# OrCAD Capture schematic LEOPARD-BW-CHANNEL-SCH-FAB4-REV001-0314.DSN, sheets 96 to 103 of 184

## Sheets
96 078_CPU SIDE BAND - FIVR FAULT: size A3; title: CPU SIDE BAND - FIVR FAULT
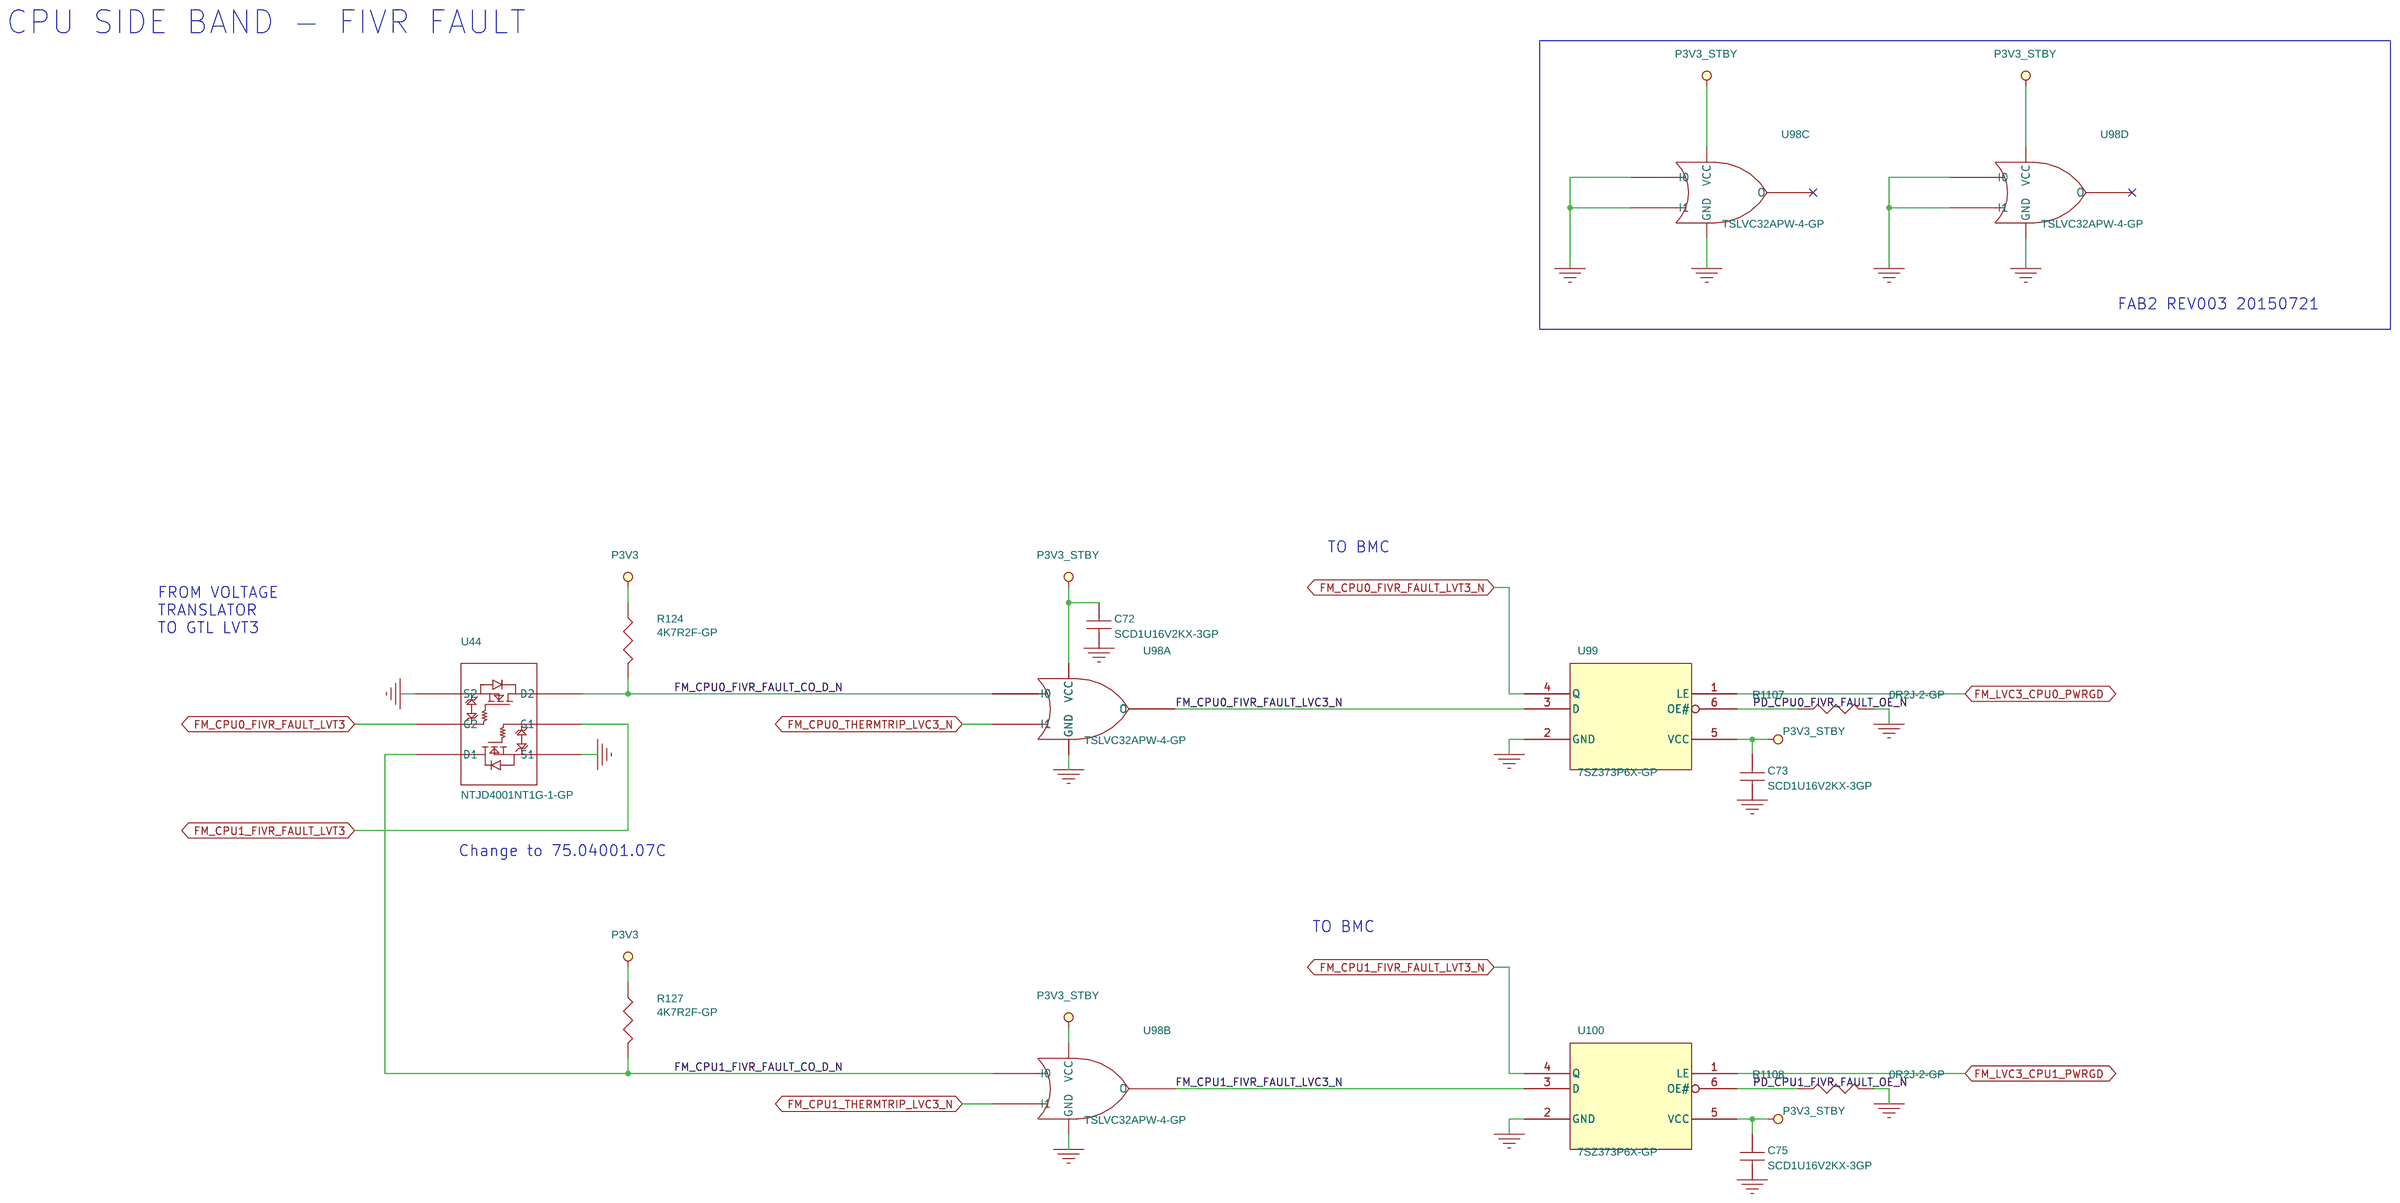
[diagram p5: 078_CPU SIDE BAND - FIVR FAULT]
97 076_CPU SIDE BAND - RST & PG: size A3; title: CPU SIDE BAND - RST & PG
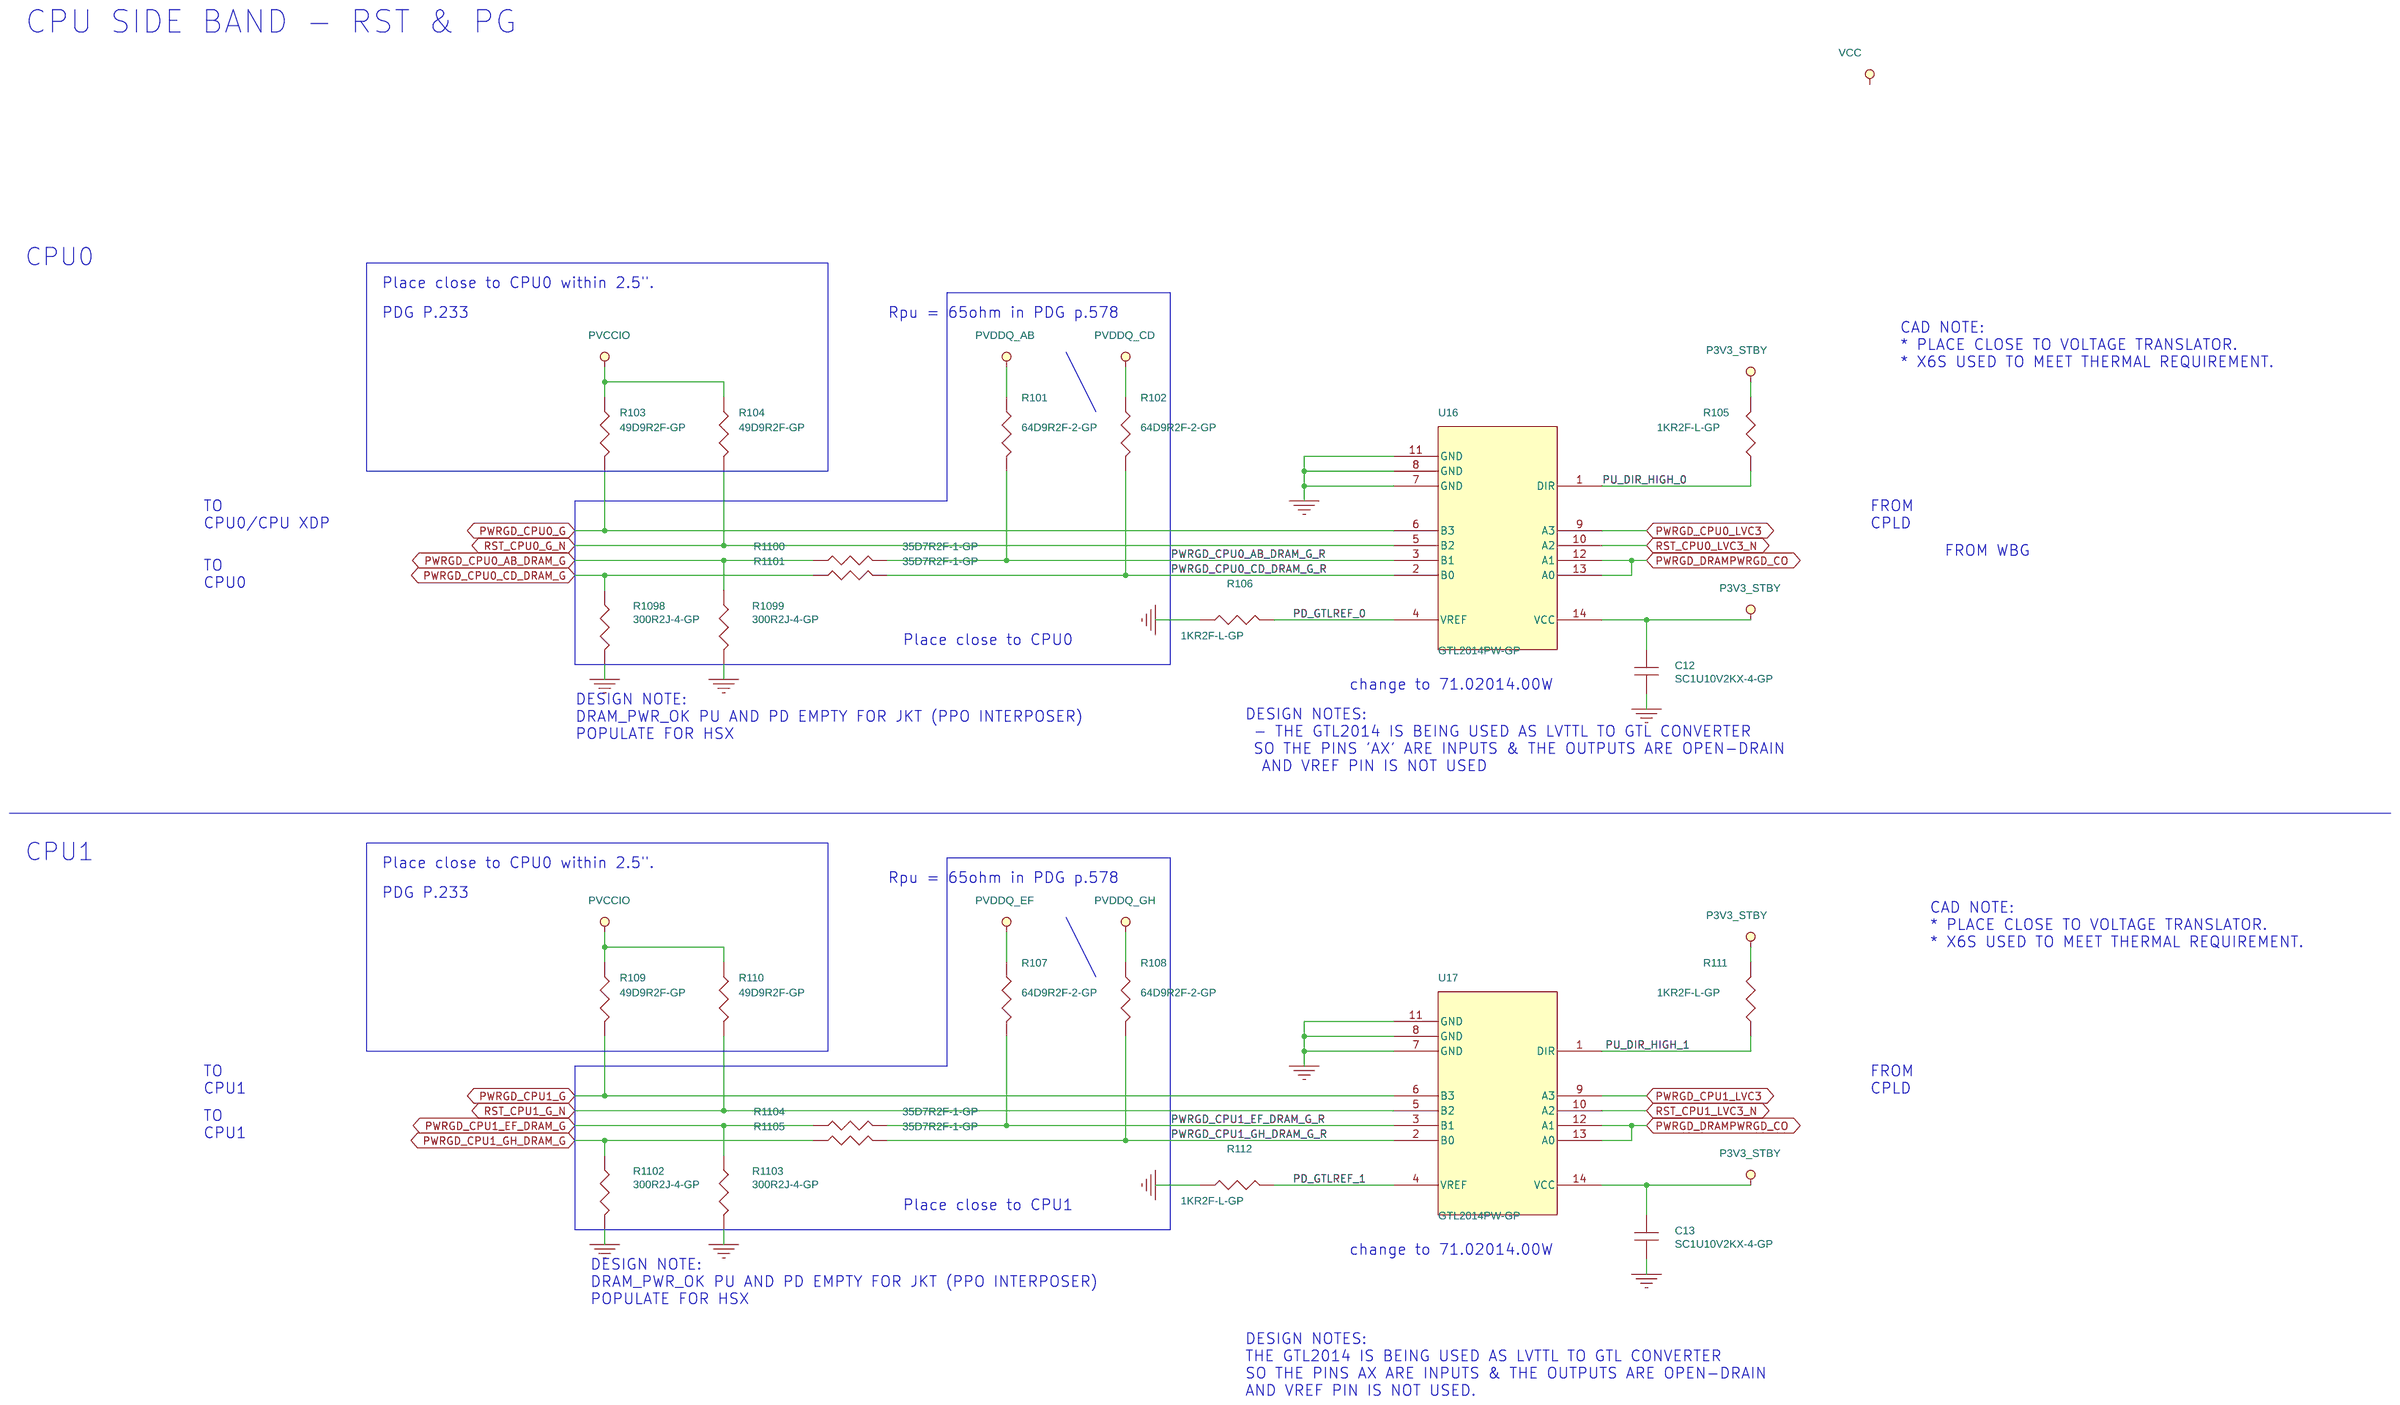
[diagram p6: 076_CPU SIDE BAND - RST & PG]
98 075_CPU SIDE BAND - DIMM_EVENT: size A3; title: CPU SIDE BAND - DIMM EVENT
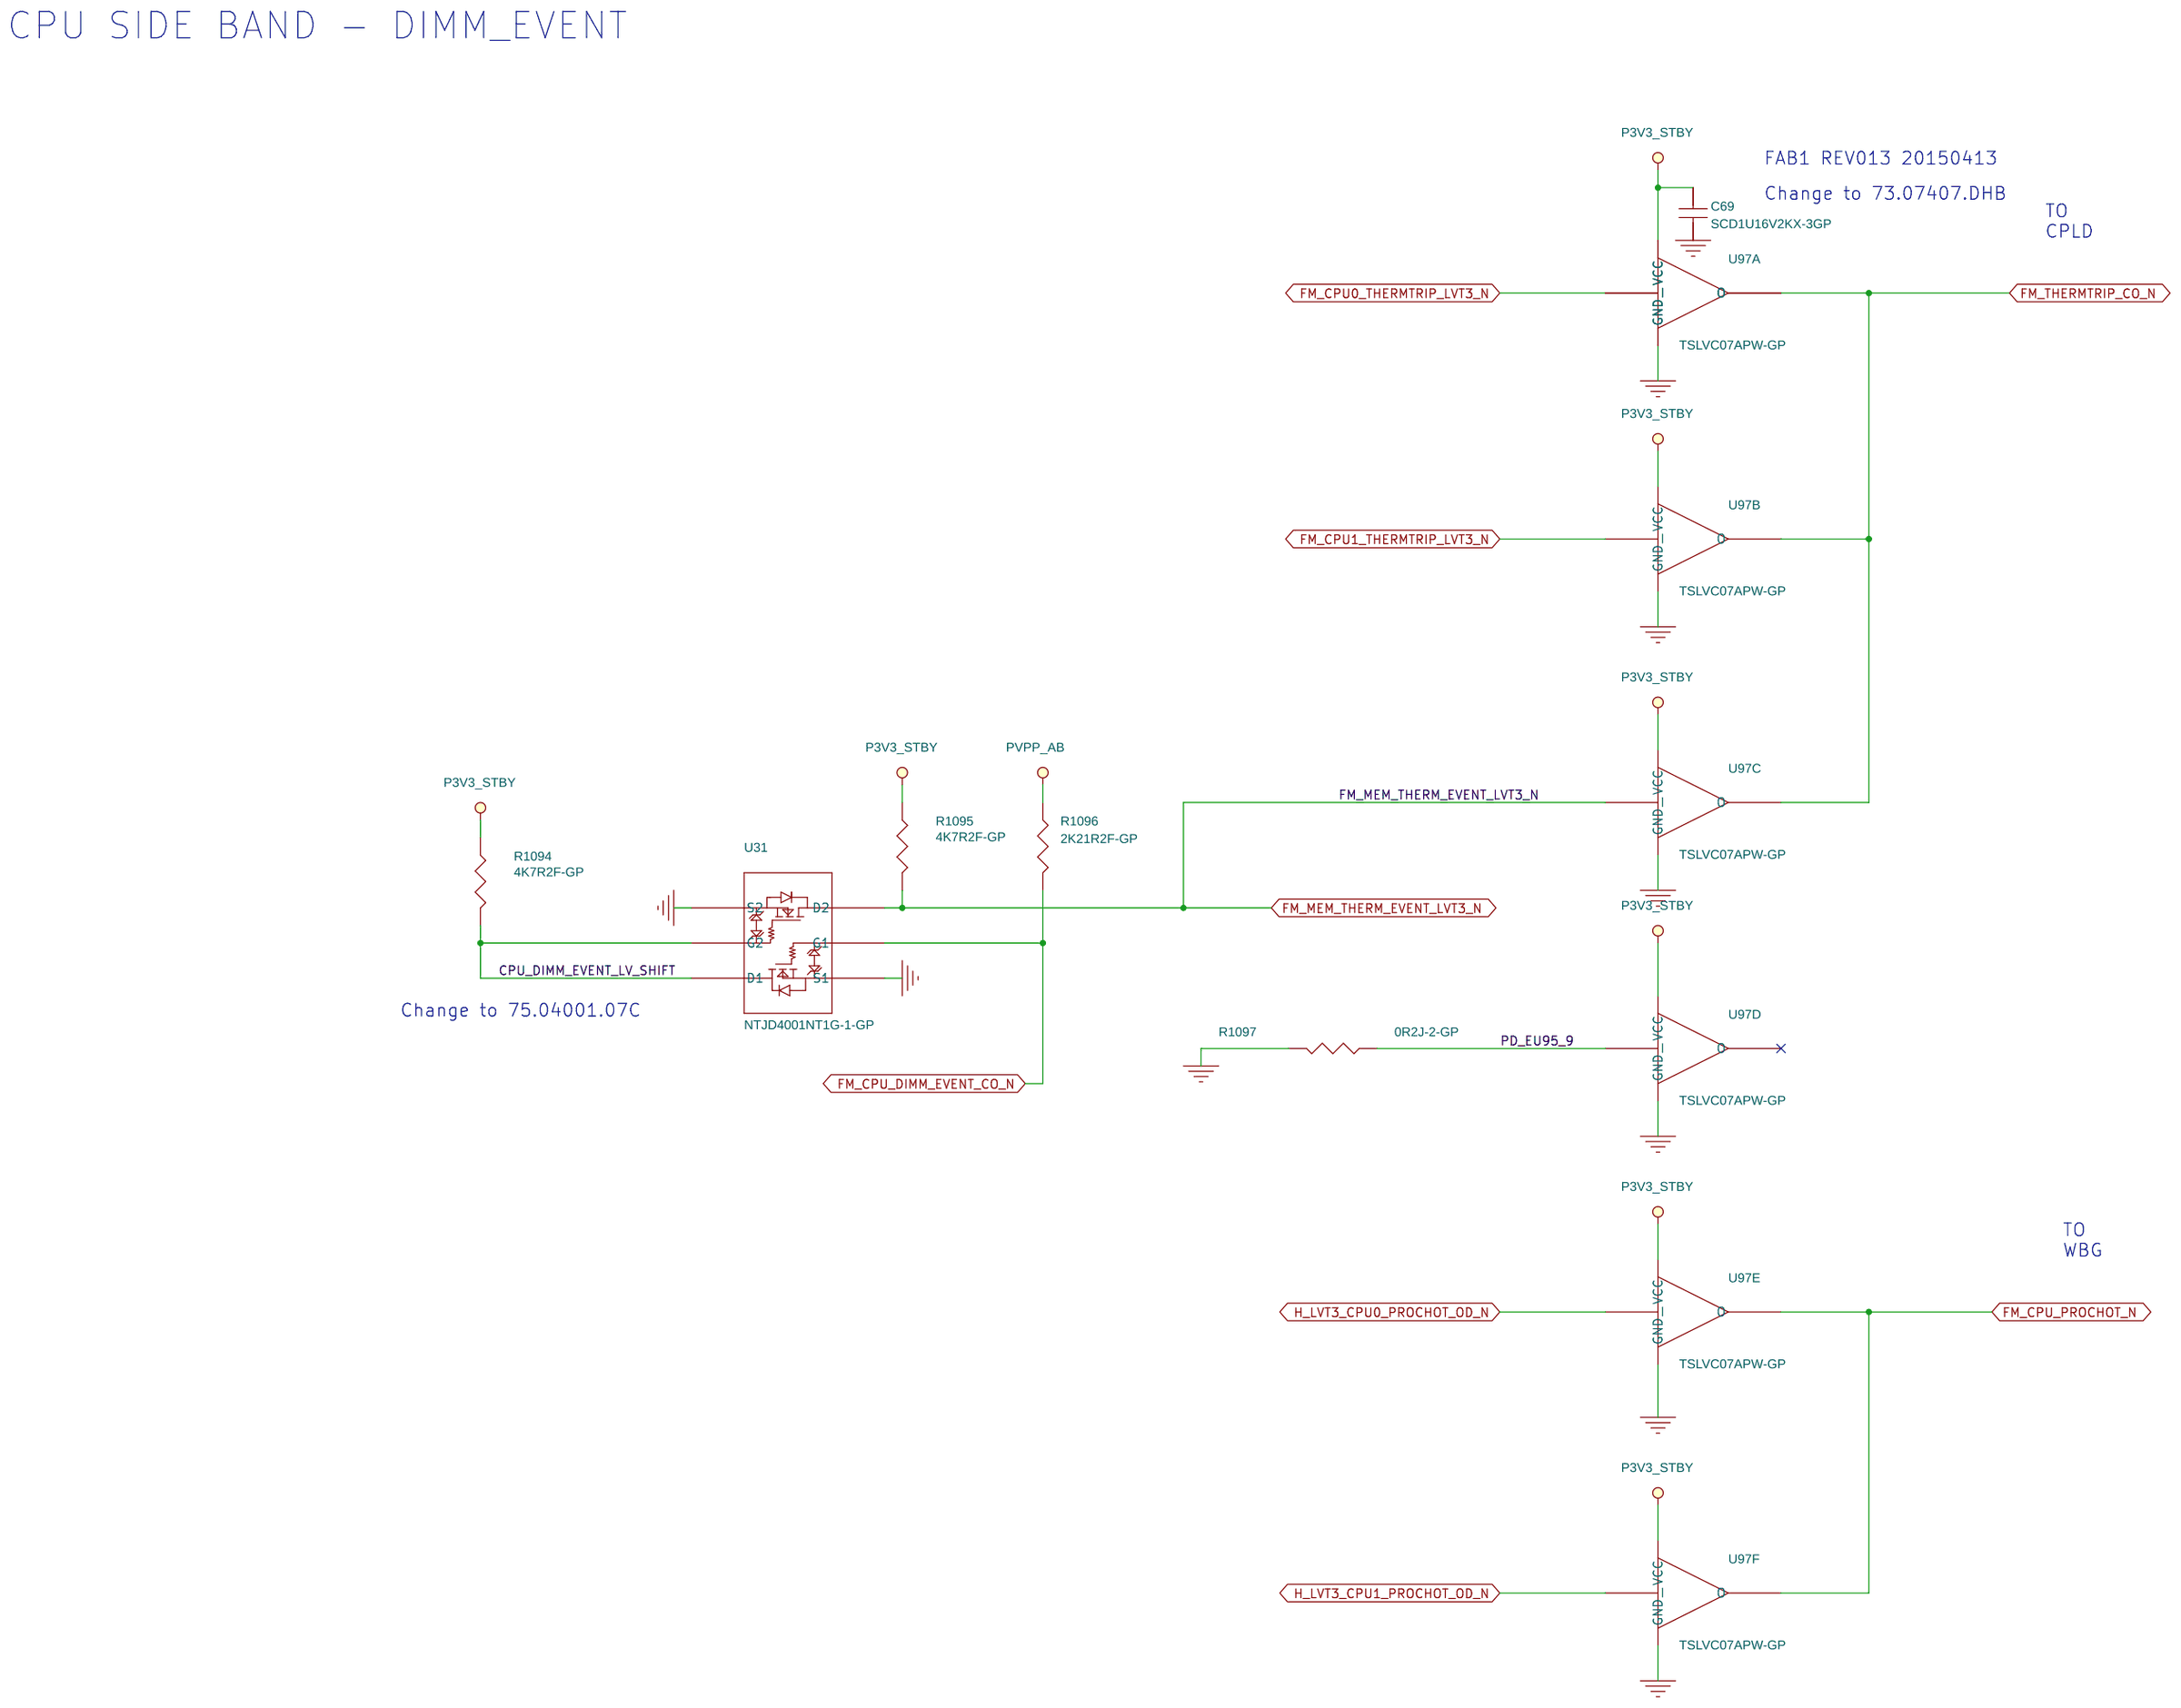
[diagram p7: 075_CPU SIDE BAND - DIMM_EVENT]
99 072_CPU SIDE BAND - THERMTRIP: size A3; title: CPU SIDE BAND - THERMTRIP
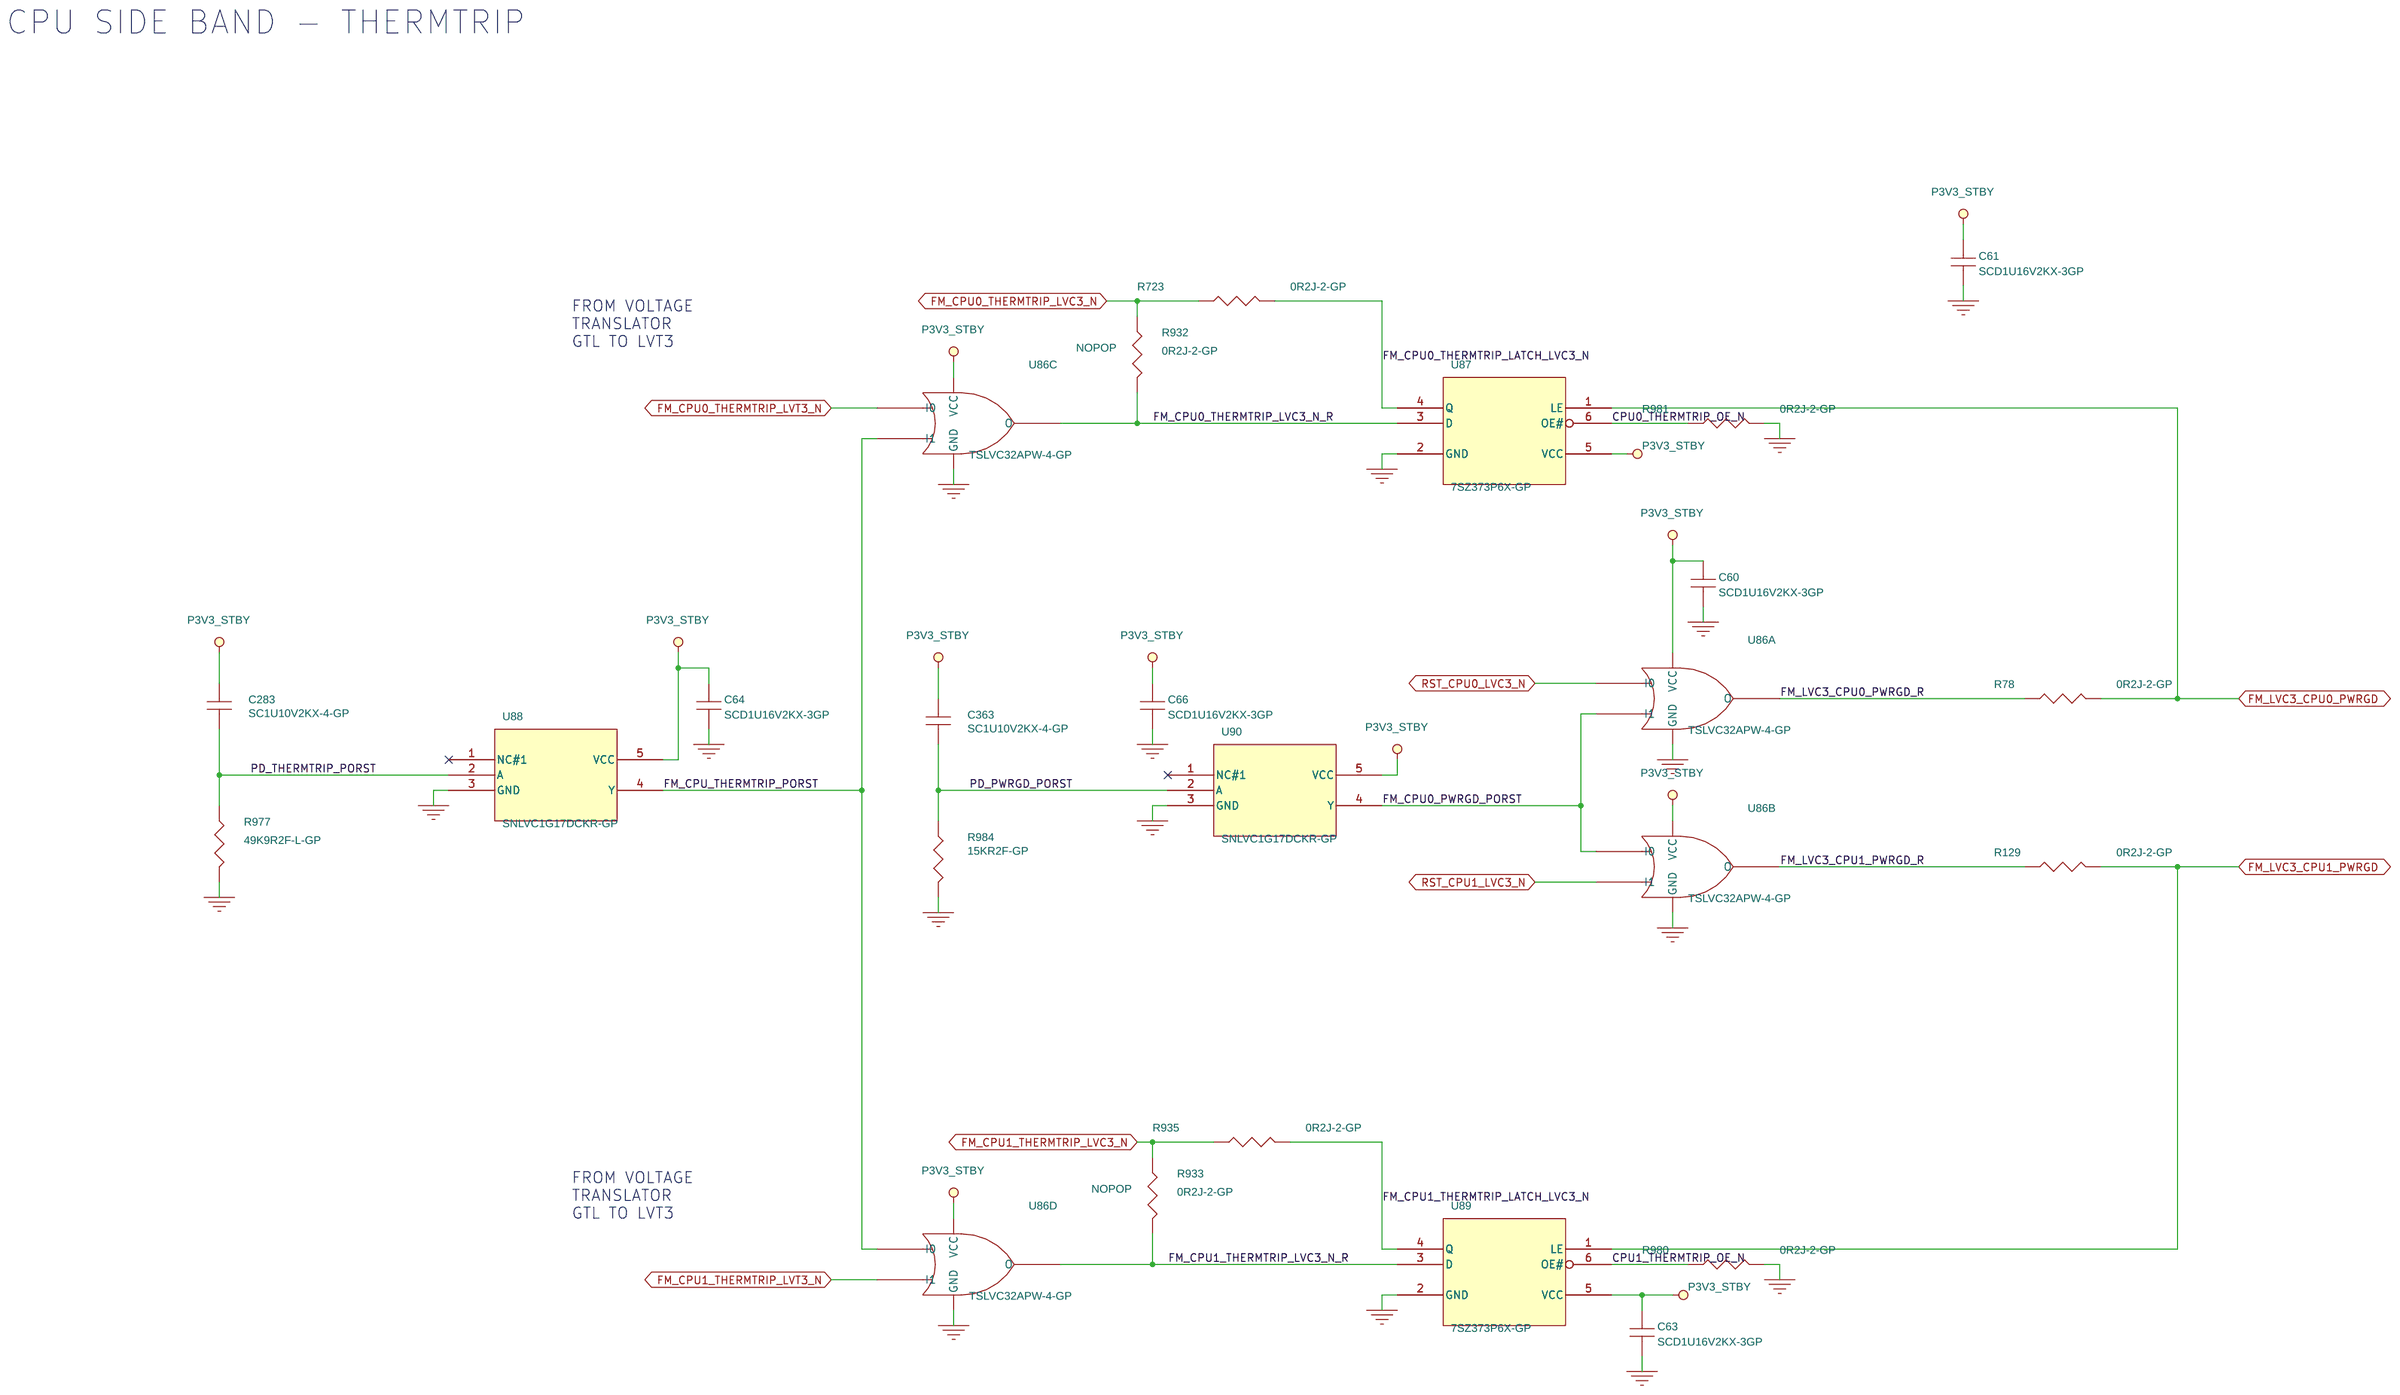
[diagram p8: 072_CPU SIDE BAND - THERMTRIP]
100 071_CPU SIDE BAND - CAT. ERROR: size A3; title: CPU SIDE BAND - CAT. ERROR
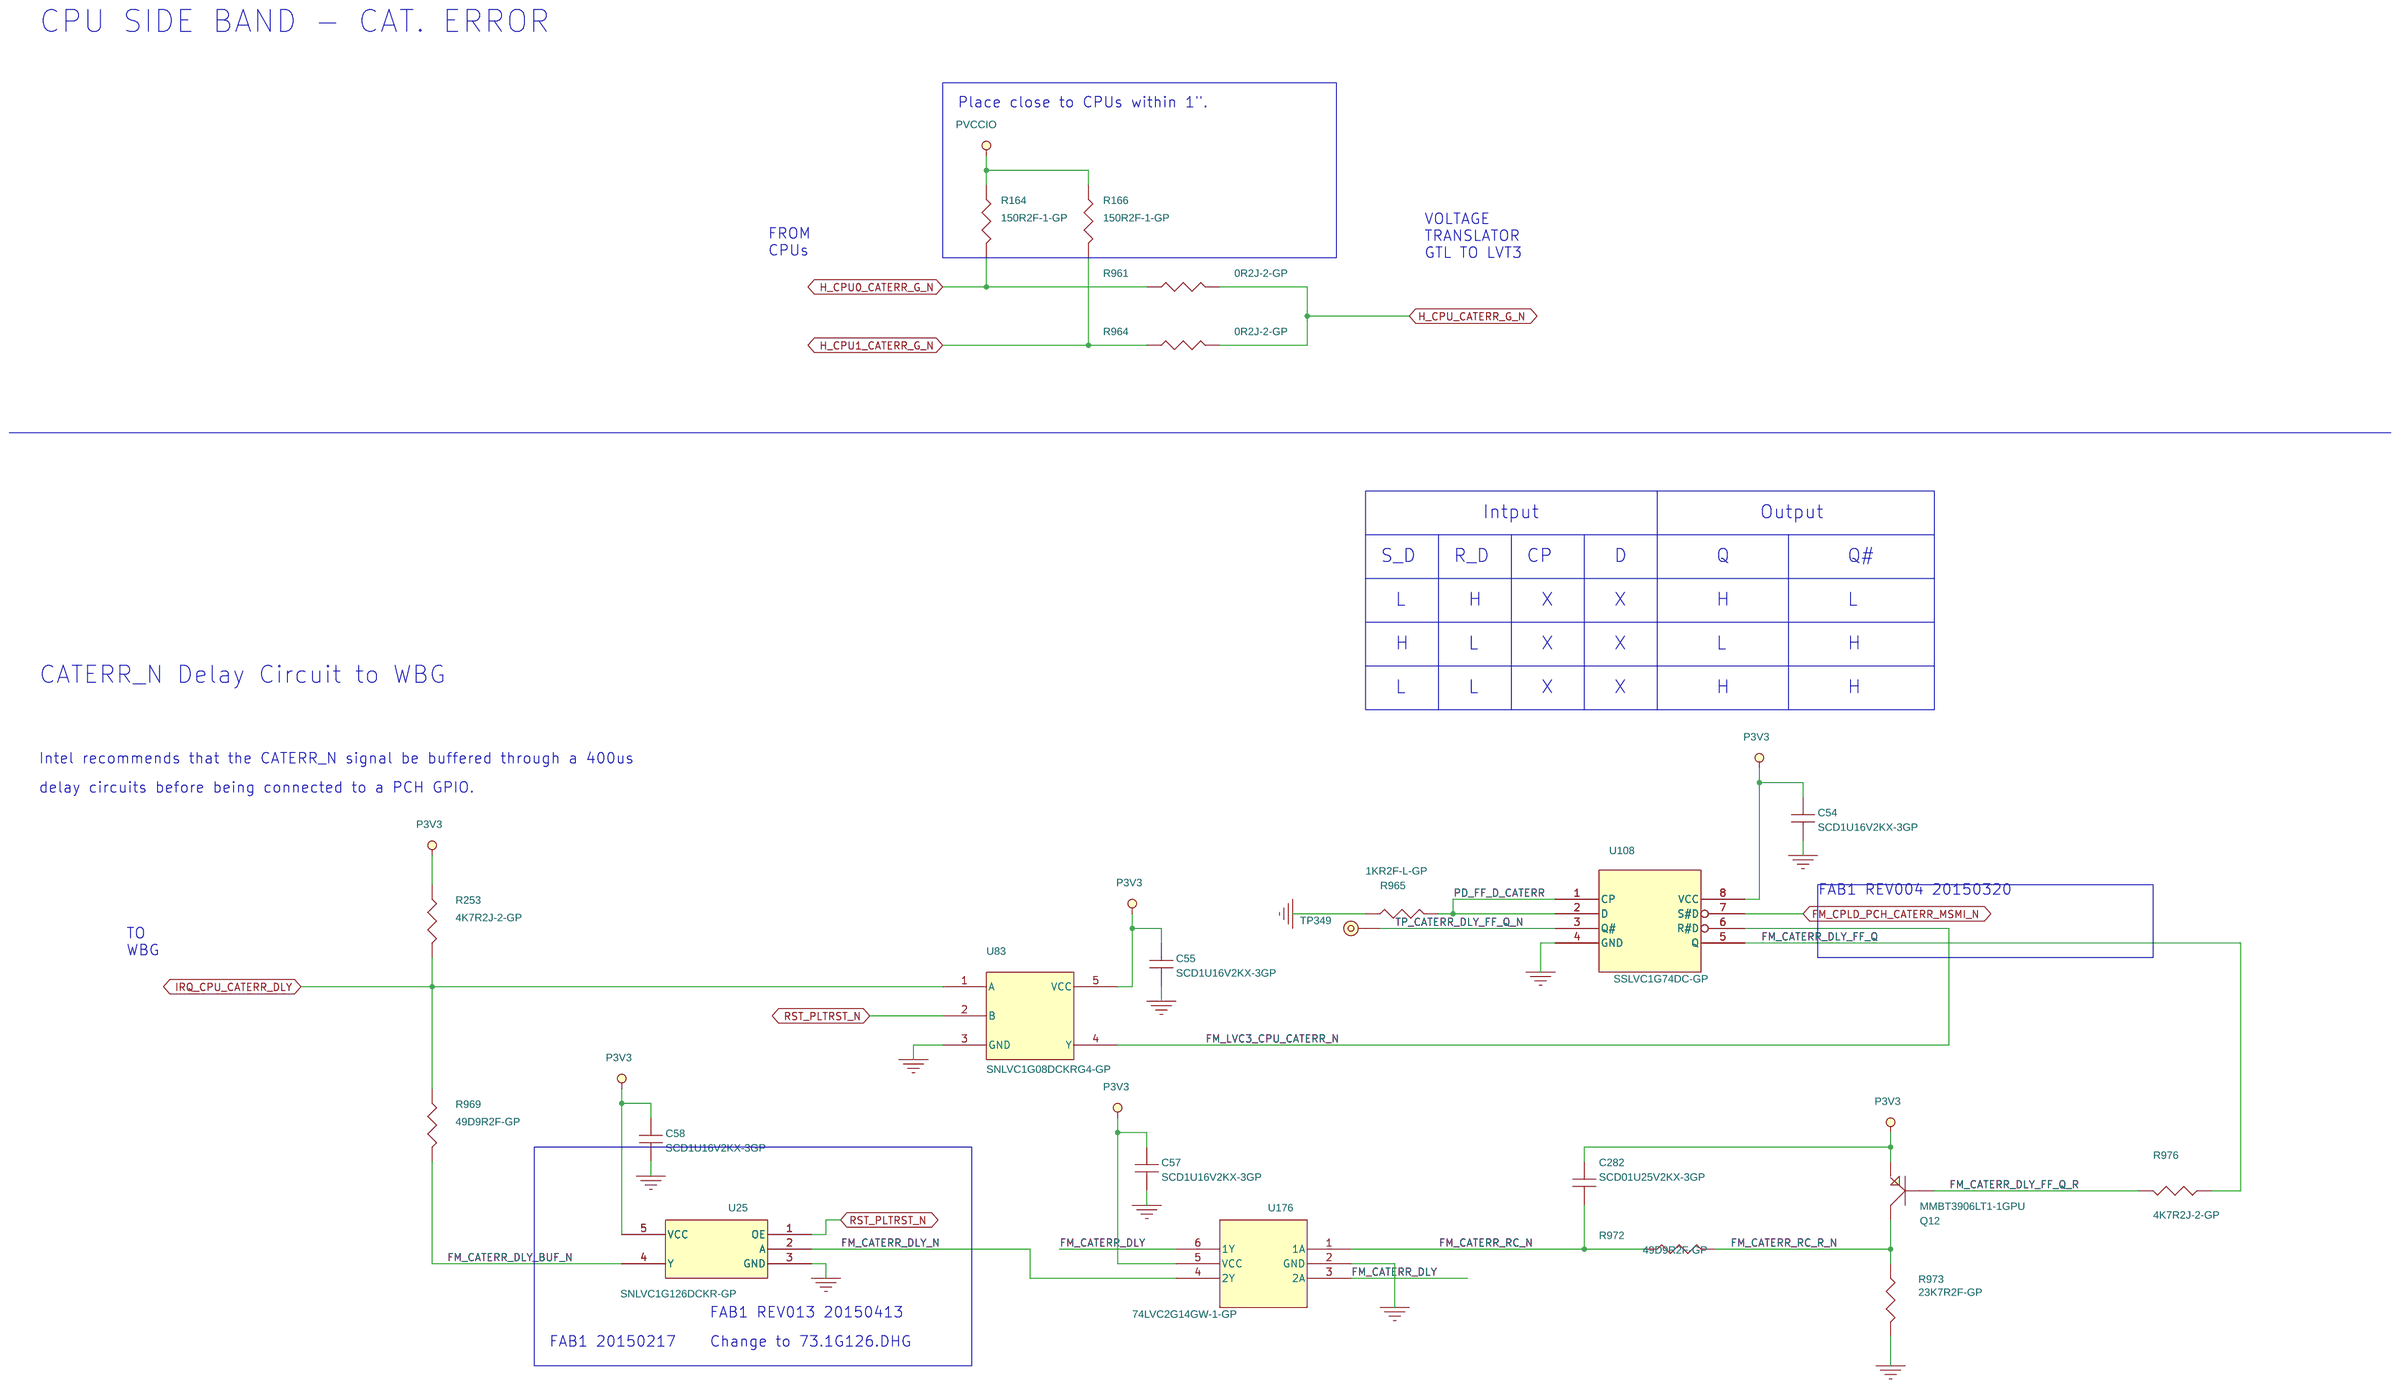
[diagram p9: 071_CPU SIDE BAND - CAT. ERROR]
101 070_CPU SIDE BAND - LEVEL SHIFT: size A3; title: CPU SIDE BAND - LEVEL SHIFT
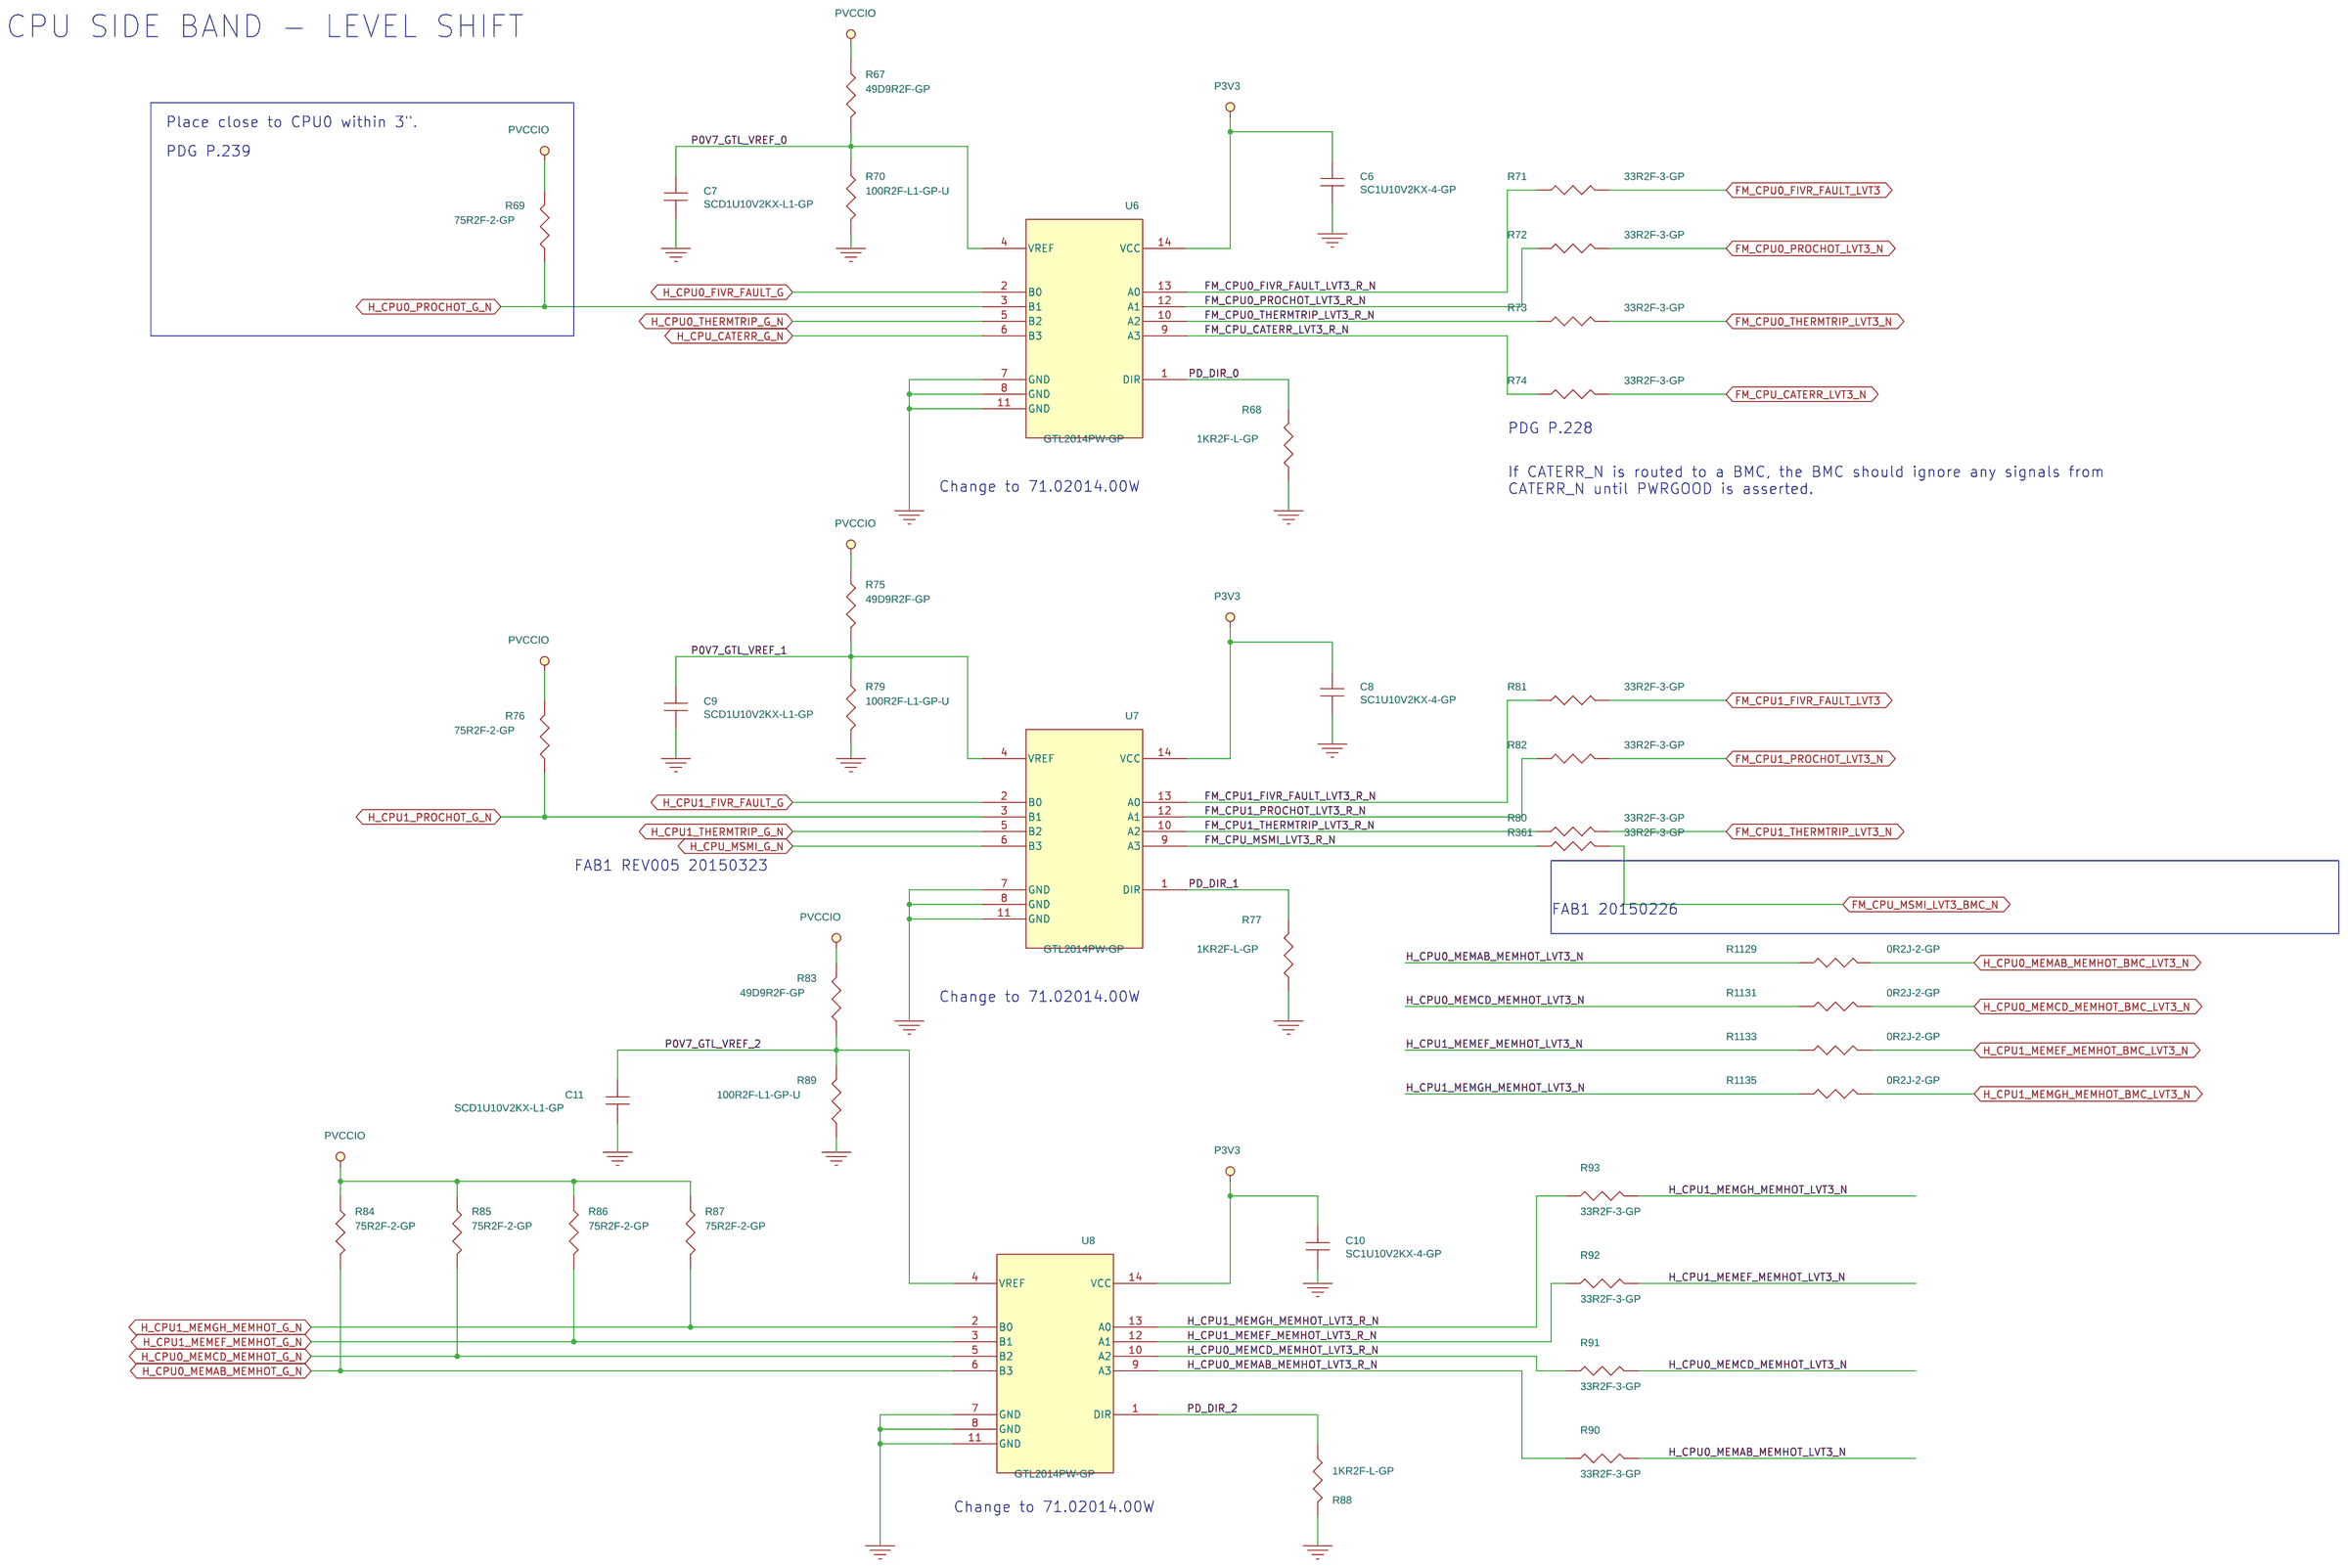
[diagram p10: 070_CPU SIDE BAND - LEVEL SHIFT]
102 069_CPU SIDE BAND - ERR CIRCUIT: size A3; title: CPU SIDE BAND - ERR CIRCUIT
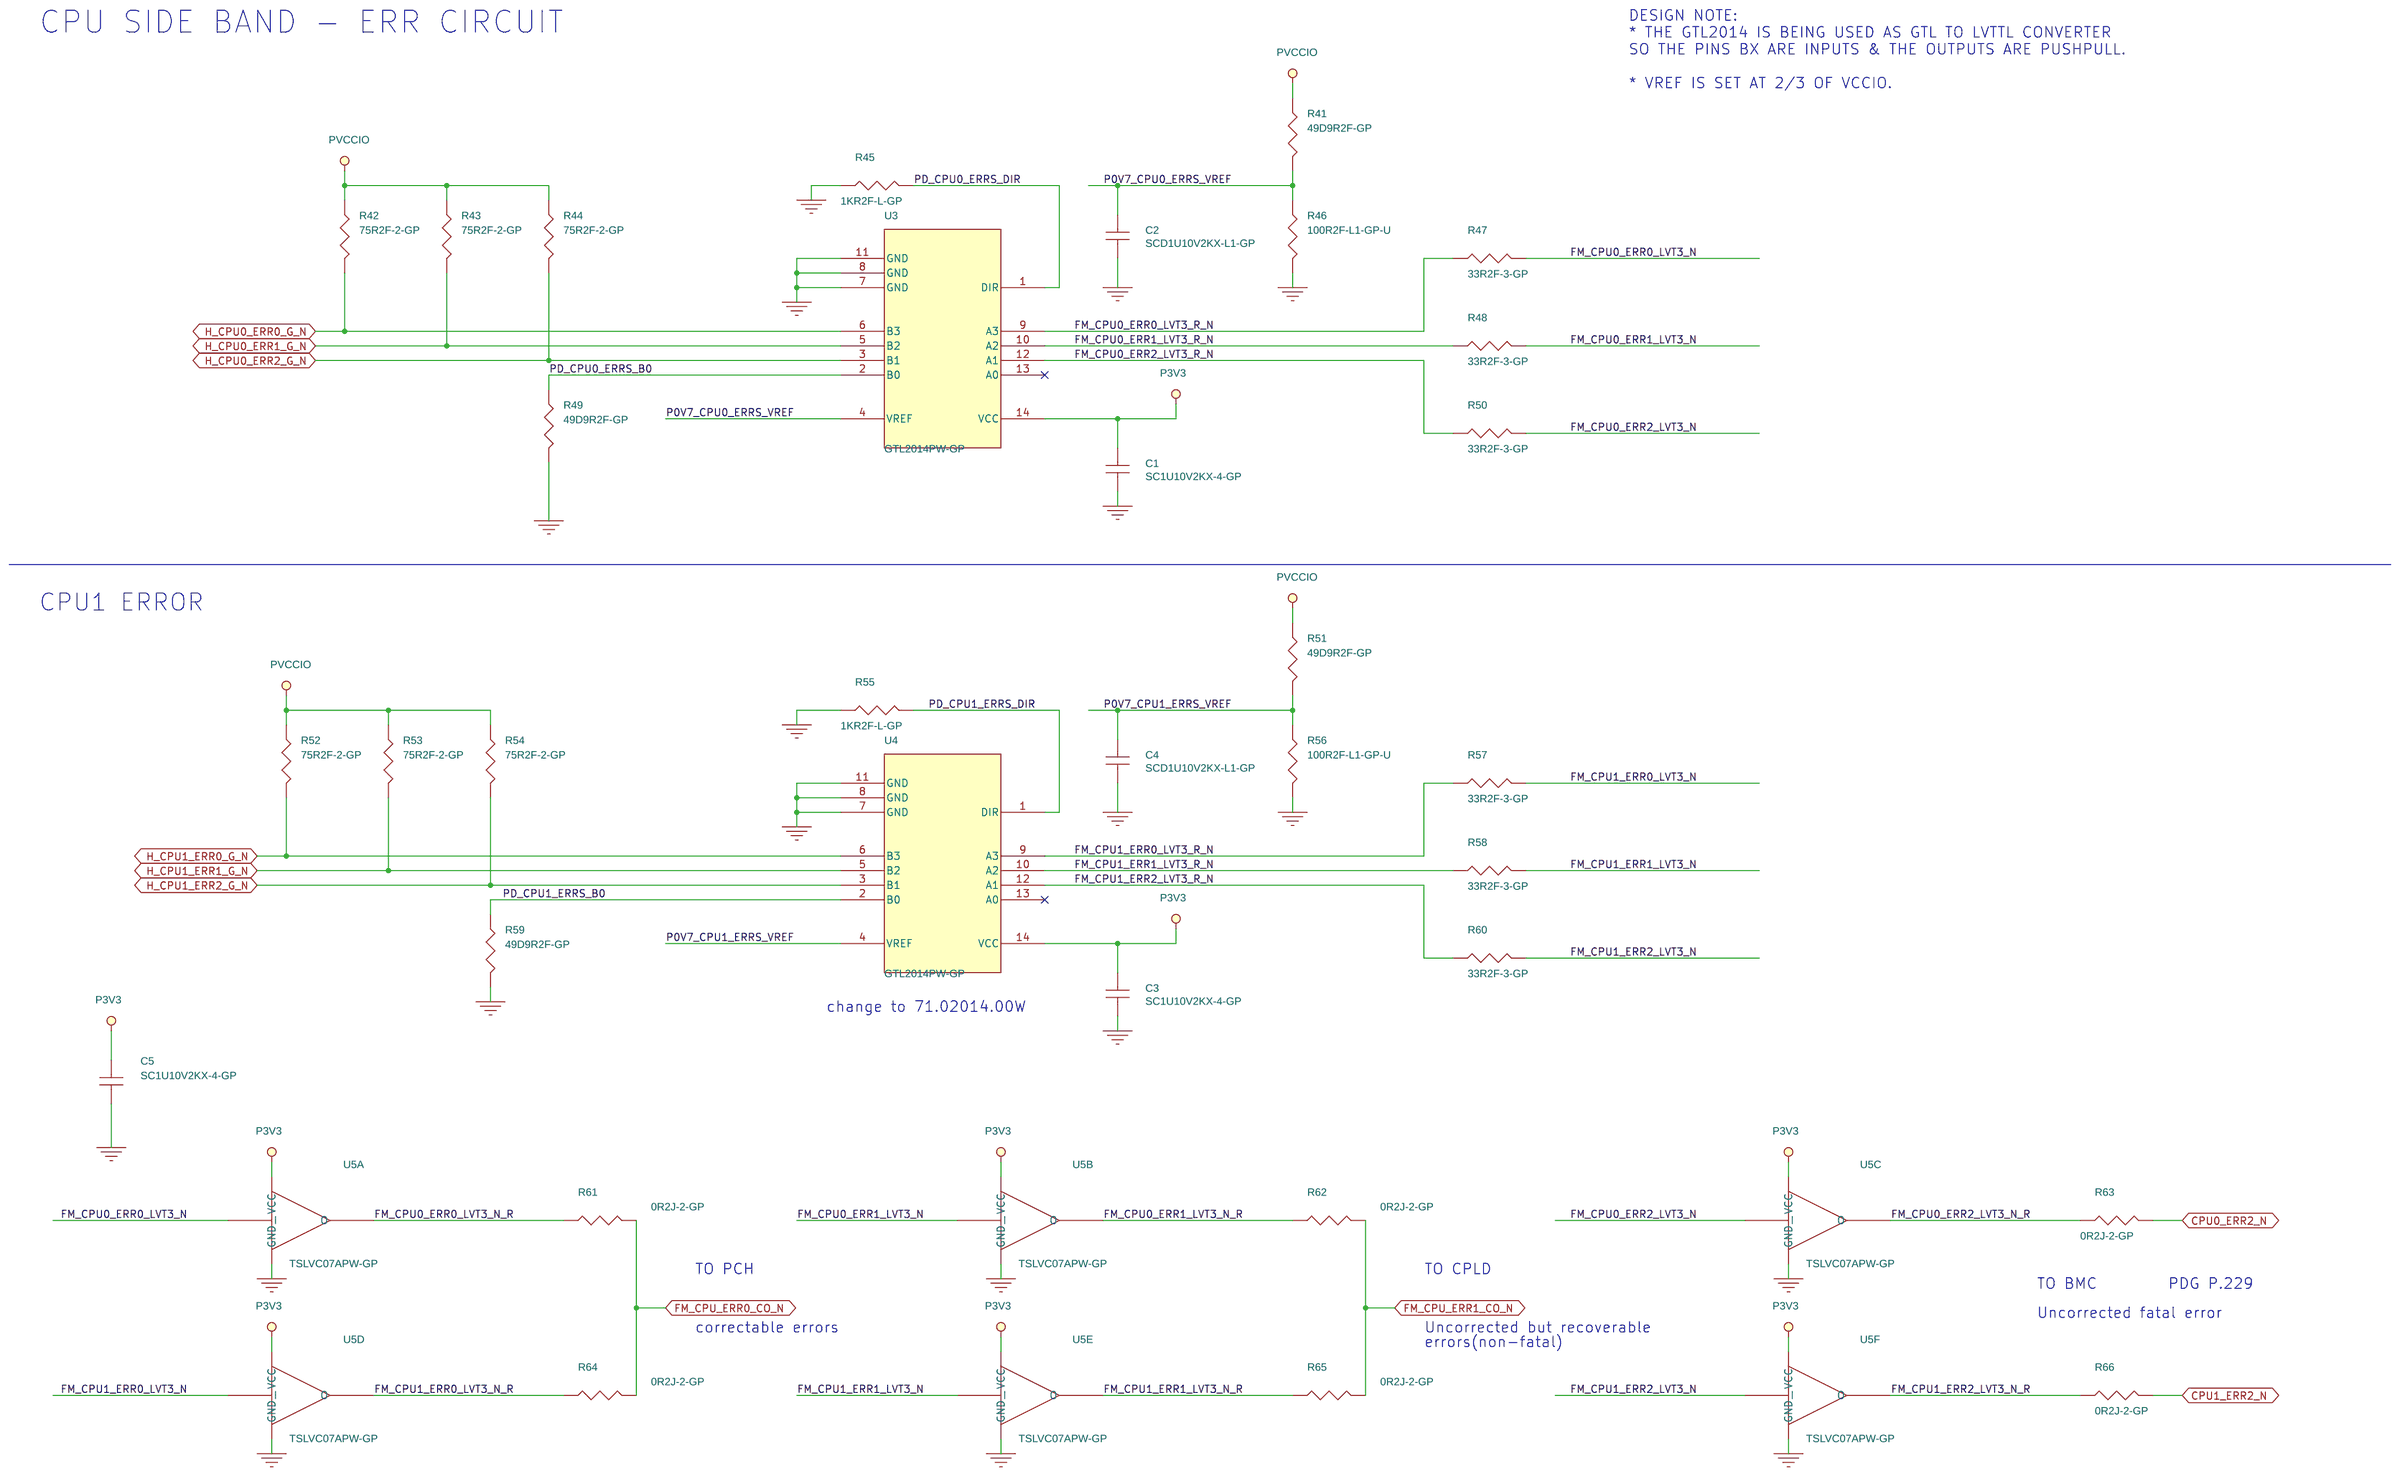
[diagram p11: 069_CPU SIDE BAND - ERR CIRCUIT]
103 068_CPU SIDE BAND - HW STRAPS: size A3; title: CPU SIDE BAND - HW STRAPS
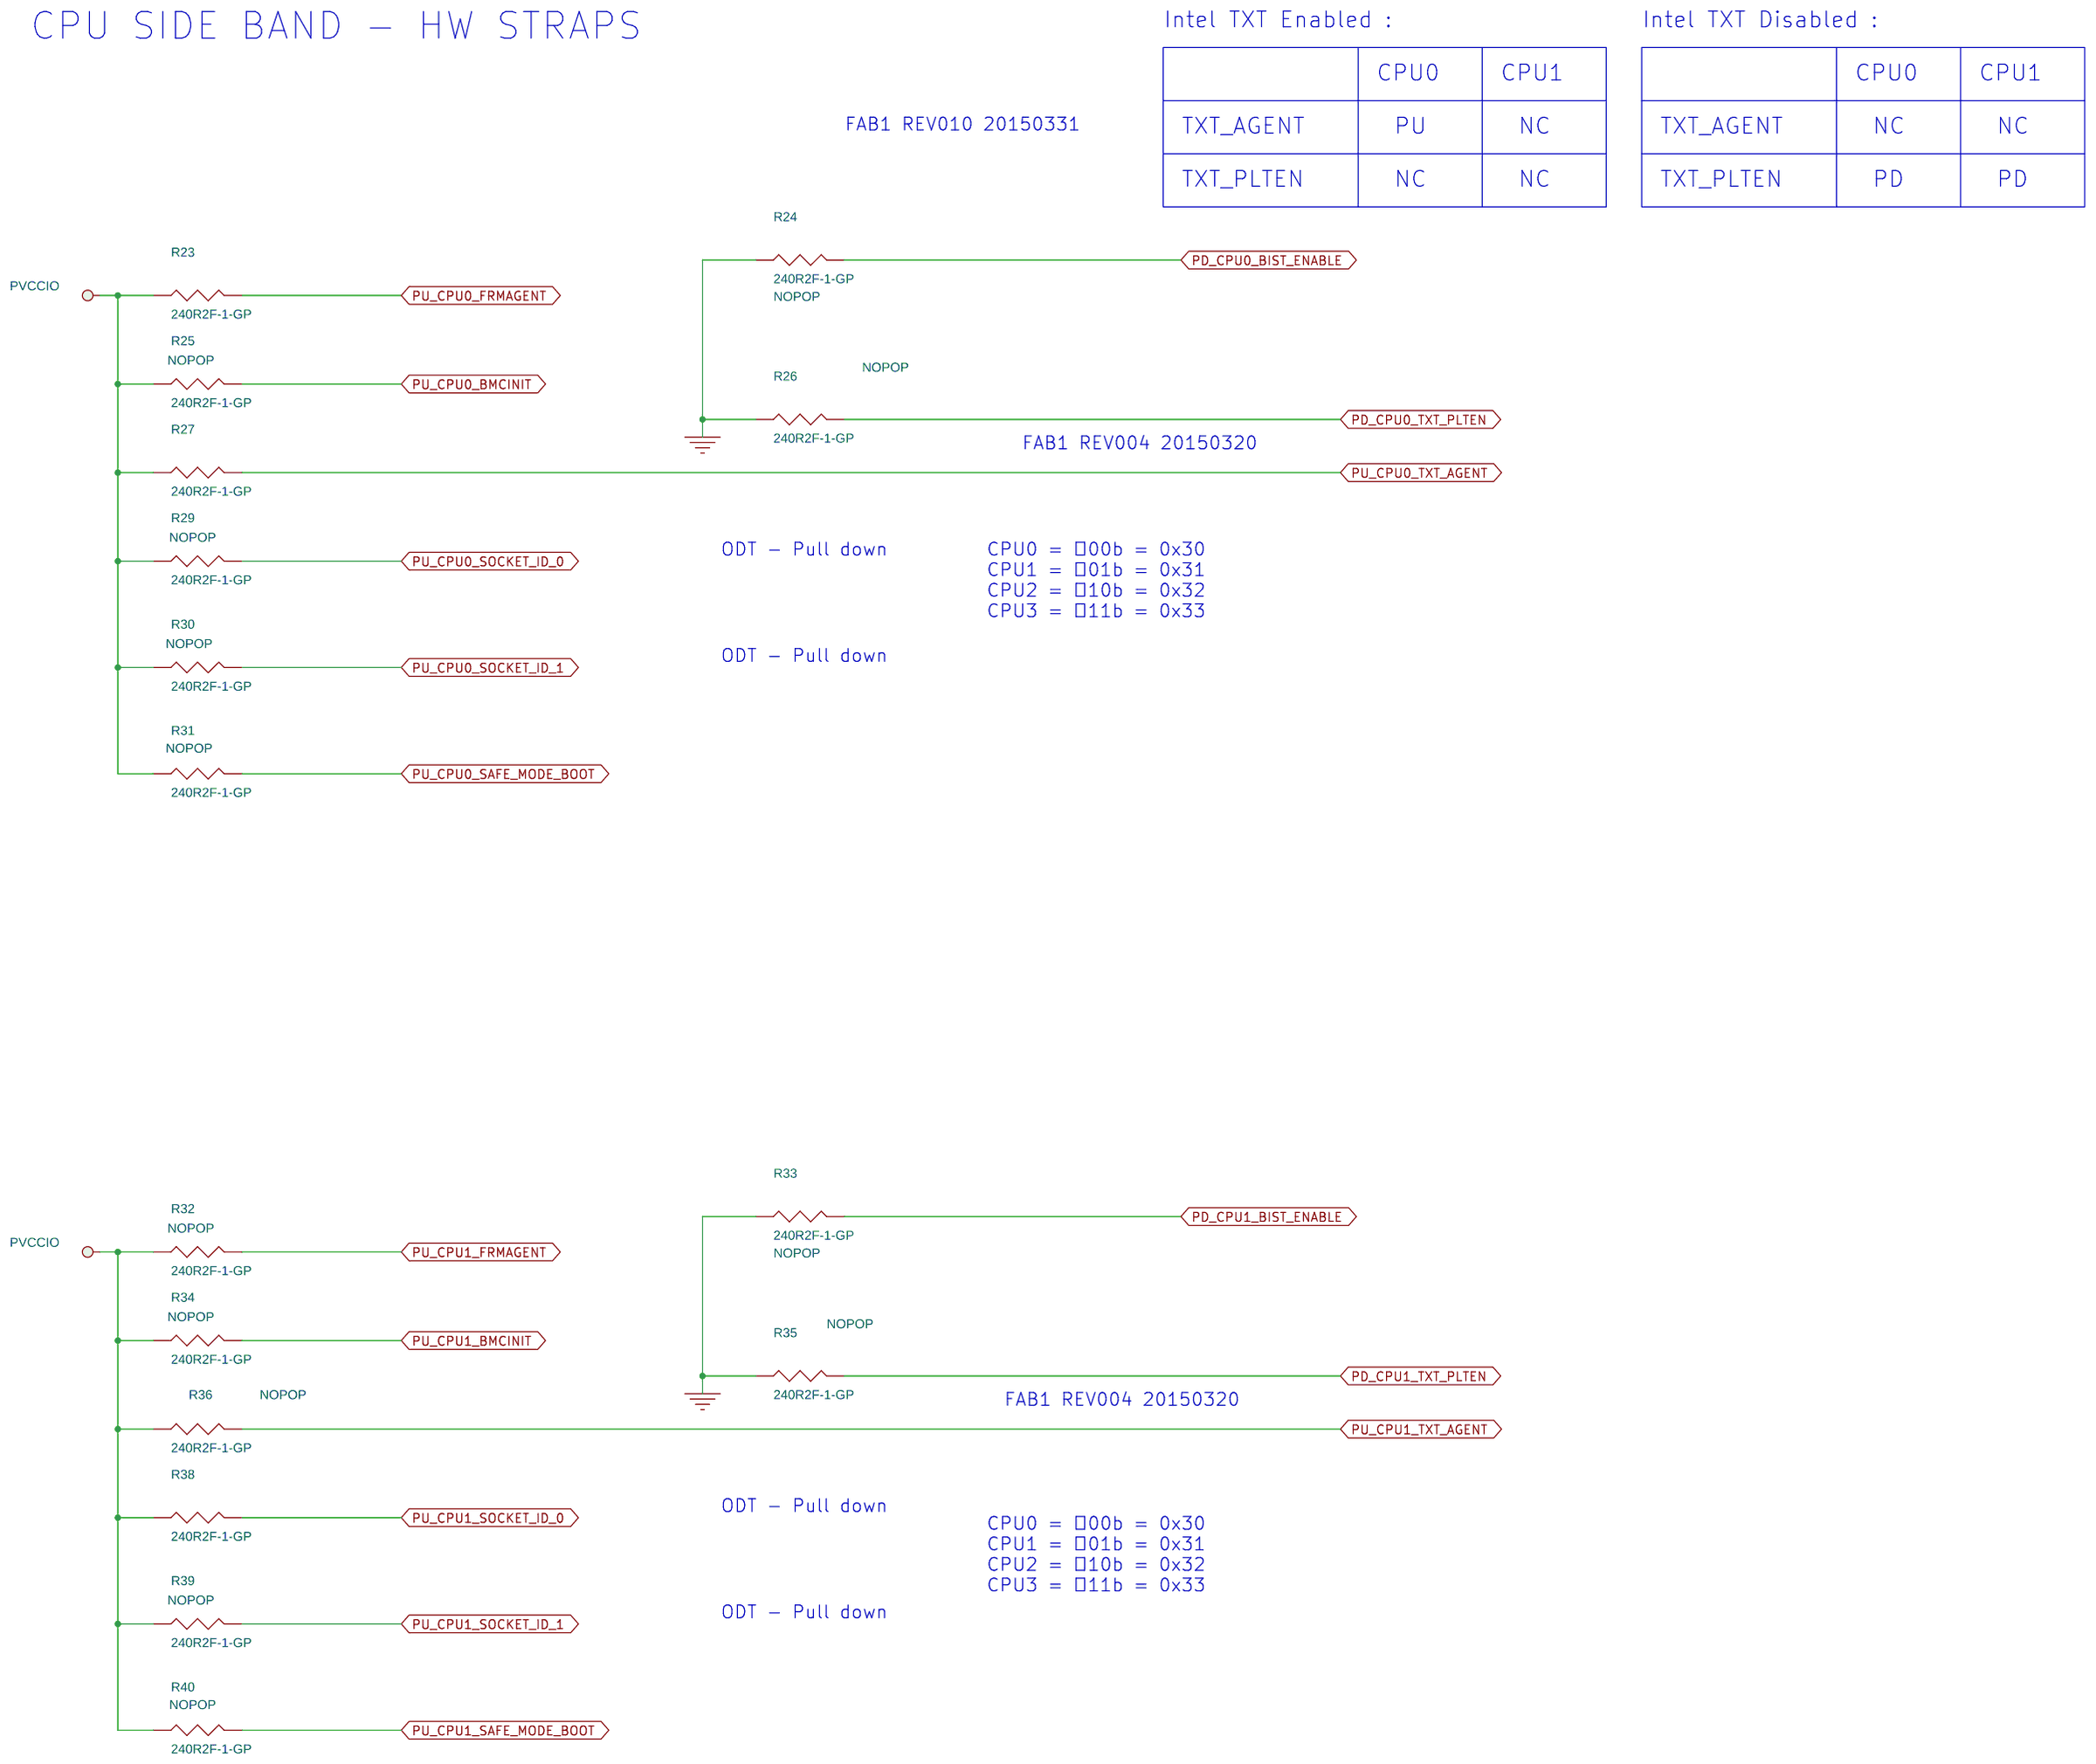
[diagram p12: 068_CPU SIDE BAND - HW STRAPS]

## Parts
sheet 068_CPU SIDE BAND - HW STRAPS
R23  240R2F-1-GP  [R402H16]
R24  240R2F-1-GP  [R402H16]
R25  240R2F-1-GP  [R402H16]
R26  240R2F-1-GP  [R402H16]
R27  240R2F-1-GP  [R402H16]
R29  240R2F-1-GP  [R402H16]
R30  240R2F-1-GP  [R402H16]
R31  240R2F-1-GP  [R402H16]
R32  240R2F-1-GP  [R402H16]
R33  240R2F-1-GP  [R402H16]
R34  240R2F-1-GP  [R402H16]
R35  240R2F-1-GP  [R402H16]
R36  240R2F-1-GP  [R402H16]
R38  240R2F-1-GP  [R402H16]
R39  240R2F-1-GP  [R402H16]
R40  240R2F-1-GP  [R402H16]
sheet 069_CPU SIDE BAND - ERR CIRCUIT
C1  SC1U10V2KX-4-GP  [C402H22]
C2  SCD1U10V2KX-L1-GP  [C402H22]
C3  SC1U10V2KX-4-GP  [C402H22]
C4  SCD1U10V2KX-L1-GP  [C402H22]
C5  SC1U10V2KX-4-GP  [C402H22]
R41  49D9R2F-GP  [R402H16]
R42  75R2F-2-GP  [R402H16]
R43  75R2F-2-GP  [R402H16]
R44  75R2F-2-GP  [R402H16]
R45  1KR2F-L-GP  [R402H16]
R46  100R2F-L1-GP-U  [R402H14]
R47  33R2F-3-GP  [R402H16]
R48  33R2F-3-GP  [R402H16]
R49  49D9R2F-GP  [R402H16]
R50  33R2F-3-GP  [R402H16]
R51  49D9R2F-GP  [R402H16]
R52  75R2F-2-GP  [R402H16]
R53  75R2F-2-GP  [R402H16]
R54  75R2F-2-GP  [R402H16]
R55  1KR2F-L-GP  [R402H16]
R56  100R2F-L1-GP-U  [R402H14]
R57  33R2F-3-GP  [R402H16]
R58  33R2F-3-GP  [R402H16]
R59  49D9R2F-GP  [R402H16]
R60  33R2F-3-GP  [R402H16]
R61  0R2J-2-GP  [R402H16]
R62  0R2J-2-GP  [R402H16]
R63  0R2J-2-GP  [R402H16]
R64  0R2J-2-GP  [R402H16]
R65  0R2J-2-GP  [R402H16]
R66  0R2J-2-GP  [R402H16]
U3  GTL2014PW-GP  [TSOIC14H44]
U4  GTL2014PW-GP  [TSOIC14H44]
U5  TSLVC07APW-GP  [TSOIC14H44]  (sections A,B,C,D,E,F)
sheet 070_CPU SIDE BAND - LEVEL SHIFT
C6  SC1U10V2KX-4-GP  [C402H22]
C7  SCD1U10V2KX-L1-GP  [C402H22]
C8  SC1U10V2KX-4-GP  [C402H22]
C9  SCD1U10V2KX-L1-GP  [C402H22]
C10  SC1U10V2KX-4-GP  [C402H22]
C11  SCD1U10V2KX-L1-GP  [C402H22]
R67  49D9R2F-GP  [R402H16]
R68  1KR2F-L-GP  [R402H16]
R69  75R2F-2-GP  [R402H16]
R70  100R2F-L1-GP-U  [R402H14]
R71  33R2F-3-GP  [R402H16]
R72  33R2F-3-GP  [R402H16]
R73  33R2F-3-GP  [R402H16]
R74  33R2F-3-GP  [R402H16]
R75  49D9R2F-GP  [R402H16]
R76  75R2F-2-GP  [R402H16]
R77  1KR2F-L-GP  [R402H16]
R79  100R2F-L1-GP-U  [R402H14]
R80  33R2F-3-GP  [R402H16]
R81  33R2F-3-GP  [R402H16]
R82  33R2F-3-GP  [R402H16]
R83  49D9R2F-GP  [R402H16]
R84  75R2F-2-GP  [R402H16]
R85  75R2F-2-GP  [R402H16]
R86  75R2F-2-GP  [R402H16]
R87  75R2F-2-GP  [R402H16]
R88  1KR2F-L-GP  [R402H16]
R89  100R2F-L1-GP-U  [R402H14]
R90  33R2F-3-GP  [R402H16]
R91  33R2F-3-GP  [R402H16]
R92  33R2F-3-GP  [R402H16]
R93  33R2F-3-GP  [R402H16]
R361  33R2F-3-GP  [R402H16]
R1129  0R2J-2-GP  [R402H16]
R1131  0R2J-2-GP  [R402H16]
R1133  0R2J-2-GP  [R402H16]
R1135  0R2J-2-GP  [R402H16]
U6  GTL2014PW-GP  [TSOIC14H44]
U7  GTL2014PW-GP  [TSOIC14H44]
U8  GTL2014PW-GP  [TSOIC14H44]
sheet 071_CPU SIDE BAND - CAT. ERROR
C54  SCD1U16V2KX-3GP  [C402H22]
C55  SCD1U16V2KX-3GP  [C402H22]
C57  SCD1U16V2KX-3GP  [C402H22]
C58  SCD1U16V2KX-3GP  [C402H22]
C282  SCD01U25V2KX-3GP  [C402H22]
Q12  MMBT3906LT1-1GPU  [SOT23CBE2D4H44]
R164  150R2F-1-GP  [R402H16]
R166  150R2F-1-GP  [R402H16]
R253  4K7R2J-2-GP  [R402H16]
R961  0R2J-2-GP  [R402H16]
R964  0R2J-2-GP  [R402H16]
R965  1KR2F-L-GP  [R402H16]
R969  49D9R2F-GP  [R402H16]
R972  49D9R2F-GP  [R402H16]
R973  23K7R2F-GP  [R402H16]
R976  4K7R2J-2-GP  [R402H16]
TP349  TPAD24  [TPAD24]
U25  SNLVC1G126DCKR-GP  [SC70-5H44]
U83  SNLVC1G08DCKRG4-GP  [SC70-5H44]
U108  SSLVC1G74DC-GP  [SSOIC8-4H40]
U176  74LVC2G14GW-1-GP  [SC70-6H44]
sheet 072_CPU SIDE BAND - THERMTRIP
C60  SCD1U16V2KX-3GP  [C402H22]
C61  SCD1U16V2KX-3GP  [C402H22]
C63  SCD1U16V2KX-3GP  [C402H22]
C64  SCD1U16V2KX-3GP  [C402H22]
C66  SCD1U16V2KX-3GP  [C402H22]
C283  SC1U10V2KX-4-GP  [C402H22]
C363  SC1U10V2KX-4-GP  [C402H22]
R78  0R2J-2-GP  [R402H16]
R129  0R2J-2-GP  [R402H16]
R723  0R2J-2-GP  [R402H16]
R932  0R2J-2-GP  [R402H16]
R933  0R2J-2-GP  [R402H16]
R935  0R2J-2-GP  [R402H16]
R977  49K9R2F-L-GP  [R402H16]
R980  0R2J-2-GP  [R402H16]
R981  0R2J-2-GP  [R402H16]
R984  15KR2F-GP  [R402H16]
U86  TSLVC32APW-4-GP  [TSOIC14H44]  (sections A,B,C,D)
U87  7SZ373P6X-GP  [SC70-6H44]
U88  SNLVC1G17DCKR-GP  [SC70-5H44]
U89  7SZ373P6X-GP  [SC70-6H44]
U90  SNLVC1G17DCKR-GP  [SC70-5H44]
sheet 075_CPU SIDE BAND - DIMM_EVENT
C69  SCD1U16V2KX-3GP  [C402H22]
R1094  4K7R2F-GP  [R402H16]
R1095  4K7R2F-GP  [R402H16]
R1096  2K21R2F-GP  [R402H16]
R1097  0R2J-2-GP  [R402H16]
U31  NTJD4001NT1G-1-GP  [SOT-363H44]
U97  TSLVC07APW-GP  [TSOIC14H44]  (sections A,B,C,D,E,F)
sheet 076_CPU SIDE BAND - RST & PG
C12  SC1U10V2KX-4-GP  [C402H22]
C13  SC1U10V2KX-4-GP  [C402H22]
R101  64D9R2F-2-GP  [R402H16]
R102  64D9R2F-2-GP  [R402H16]
R103  49D9R2F-GP  [R402H16]
R104  49D9R2F-GP  [R402H16]
R105  1KR2F-L-GP  [R402H16]
R106  1KR2F-L-GP  [R402H16]
R107  64D9R2F-2-GP  [R402H16]
R108  64D9R2F-2-GP  [R402H16]
R109  49D9R2F-GP  [R402H16]
R110  49D9R2F-GP  [R402H16]
R111  1KR2F-L-GP  [R402H16]
R112  1KR2F-L-GP  [R402H16]
R1098  300R2J-4-GP  [R402H16]
R1099  300R2J-4-GP  [R402H16]
R1100  35D7R2F-1-GP  [R402H16]
R1101  35D7R2F-1-GP  [R402H16]
R1102  300R2J-4-GP  [R402H16]
R1103  300R2J-4-GP  [R402H16]
R1104  35D7R2F-1-GP  [R402H16]
R1105  35D7R2F-1-GP  [R402H16]
U16  GTL2014PW-GP  [TSOIC14H44]
U17  GTL2014PW-GP  [TSOIC14H44]
sheet 078_CPU SIDE BAND - FIVR FAULT
C72  SCD1U16V2KX-3GP  [C402H22]
C73  SCD1U16V2KX-3GP  [C402H22]
C75  SCD1U16V2KX-3GP  [C402H22]
R124  4K7R2F-GP  [R402H16]
R127  4K7R2F-GP  [R402H16]
R1107  0R2J-2-GP  [R402H16]
R1108  0R2J-2-GP  [R402H16]
U44  NTJD4001NT1G-1-GP  [SOT-363H44]
U98  TSLVC32APW-4-GP  [TSOIC14H44]  (sections A,B,C,D)
U99  7SZ373P6X-GP  [SC70-6H44]
U100  7SZ373P6X-GP  [SC70-6H44]

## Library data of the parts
R23 R27 R38 = 240R2F-1-GP: CHIP RES 240 F 1/16W 0402(ROHS; Category: CPU SIDE BAND; Part Number: 64.24005.6DL; Part Type: SMD-RG
R24-R26 R29-R36 R39 R40 = 240R2F-1-GP: CHIP RES 240 F 1/16W 0402(ROHS; Category: CPU SIDE BAND; POP?: NOPOP; Part Number: 64.24005.6DL; Part Type: SMD-RG
C1 C3 C5 C6 C8 C10 C12 C13 C283 C363 = SC1U10V2KX-4-GP: CHIP CAP C 1U 10V K 0402 X6S; GREENDFACTOR: R2_SA;HF_SA;; Part Number: 78.10523.8FL; Part Type: SMD-BCG6; SPEC: http://wpqssvr.wistron.com.tw:7001/wpqs/servlet/COM.qpart.Attachment?PartNumber=78.10523.8FL
C2 C4 C7 C9 C11 = SCD1U10V2KX-L1-GP: CHIP CAP C 0.1U 10V K0402 X7R 13" REEL; Category: CPU SIDE BAND; Part Number: 78.10423.L1L; Part Type: SMD-BCG6
R41 R49 R51 R59 R67 R75 R83 R103 R104 R109 R110 R969 R972 = 49D9R2F-GP: CHIP RES 49.9 F 1/16W 0402; Category: CPU SIDE BAND; Part Number: 64.49R95.6DL; Part Type: RCL_GP
R42-R44 R52-R54 R69 R76 R84-R87 = 75R2F-2-GP: CHIP RES 75 F 1/16W 0402; Category: XDP; DESCRIPTIO: CHIP RES 75 F 1/16W 0402; GREENDFACTOR: R2_SA;HF_SA;G_SA;; Package Type: SMD-RG; Part Number: 64.75R05.6DL; Part Type: SMD-RG; SPEC: http://wpqssvr.wistron.com.tw:7001/wpqs/servlet/COM.qpart.Attachment?PartNumber=64.75R05.6DL; VENDORPARTNUMBER: RM04FTN75R0 / RTT0275R0FTH / RR0510S-750-FN / RC0402FR-0775RL/WR04X75R0FTL
R45 R55 R68 R77 R88 R105 R106 R111 R112 R965 = 1KR2F-L-GP: CHIP RES 1K F 1/16W 0402; Category: CPU SIDE BAND; Part Number: 64.10015.L1L; Part Type: SMD-RG2
R46 R56 R70 R79 R89 = 100R2F-L1-GP-U: CHIP RES 100 F 1/16W 0402; Category: CPU SIDE BAND; Part Number: 64.10005.6DL; Part Type: SMD-RG
R47 R48 R50 R57 R58 R60 R71-R74 R80-R82 R90-R93 R361 = 33R2F-3-GP: CHIP RES 33 F 1/16W 0402(ROHS); Category: CPU SIDE BAND; Part Number: 64.33R05.6DL; Part Type: SMD-RG
R61-R66 R961 R964 = 0R2J-2-GP: CHIP RES 0 J 1/16W 0402; Category: PCH; DESCRIPTIO: CHIP RES 0 J 1/16W 0402; GREENDFACTOR: R2_SA;HF_SA;G_SA;; Package Type: SMD-RG; Part Number: 63.R0034.1DL; Part Type: SMD-RG; SPEC: http://wpqssvr.wistron.com.tw:7001/wpqs/servlet/COM.qpart.Attachment?PartNumber=63.R0034.1DL; VENDORPARTNUMBER: RM04JTN0/RTT02000JTH/RR0510X-000-XN/RC0402JR-070RL/WR04X000 PTL
U3 U4 U8 U16 U17 = GTL2014PW-GP: IC XLATOR GTL2014PW TSSOP 14P; GREENDFACTOR: R2_SA;; Part Number: 71.02014.00W; Part Type: DISCRET-G9; SPEC: http://wpqssvr.wistron.com.tw:7001/wpqs/servlet/COM.qpart.Attachment?PartNumber=71.02014.00W
U5 U97 = TSLVC07APW-GP: IC CMOS 74LVC07APW TSSOP 14P; Category: CPU SIDE BAND; Part Number: 73.07407.DHB; Part Type: TTL-G
R1129 R1131 R1133 R1135 = 0R2J-2-GP: CHIP RES 0 J 1/16W 0402; Category: BMC; DESCRIPTIO: CHIP RES 0 J 1/16W 0402; GREENDFACTOR: R2_SA;HF_SA;G_SA;; Package Type: SMD-RG; Part Number: 63.R0034.1DL; Part Type: SMD-RG; SPEC: http://wpqssvr.wistron.com.tw:7001/wpqs/servlet/COM.qpart.Attachment?PartNumber=63.R0034.1DL; VENDORPARTNUMBER: RM04JTN0/RTT02000JTH/RR0510X-000-XN/RC0402JR-070RL/WR04X000 PTL
U6 U7 = GTL2014PW-GP: IC XLATOR GTL2014PW TSSOP 14P; GREENDFACTOR: R_SA;; Package Type: DISCRET-G9; Part Number: 71.02014.00W; SPEC: http://wpqssvr.wistron.com.tw:7001/wpqs/servlet/COM.qpart.Attachment?PartNumber=71.02014.00W
C54 C55 C57 C58 C60 C61 C63 C64 C66 C69 C72 C73 C75 = SCD1U16V2KX-3GP: CHIP CAP C 0.1U 16V K0402 X7R; Category: CLK GEN; GREENDFACTOR: R_SA;HF_SA;G_SA;; Part Number: 78.10421.2FL; Quotation: 13_8; Type: SMD
C282 = SCD01U25V2KX-3GP: CHIP 0.01U 25V K0402 X7R(ROHS); Category: BMC; GREENDFACTOR: R2_SA;HF_SA;G_SA;; Level: SMD; Part Number: 78.10322.2FL; Part Type: SMD-BCG; SPEC: http://wpqssvr.wistron.com.tw:7001/wpqs/servlet/COM.qpart.Attachment?PartNumber=78.10322.2FL; Status: POP
Q12 = MMBT3906LT1-1GPU: XTOR MMBT3906LT1G SOT-23(ROHS); Alternate: 84.03906.R11; Category: 240VA; DESCRIPTIO: XTOR MMBT3906LT1G SOT-23(ROHS); GREENDFACTOR: R2_SA;G_SA;; Package Type: DISCRET-G; Part Number: 84.03906.G11; Part Type: DISCRET-G; SPEC: http://wpqssvr.wistron.com.tw:7001/wpqs/servlet/COM.qpart.Attachment?PartNumber=84.03906.G11; VENDORPARTNUMBER: MMBT3906LT1G; Vendor PN: MMBT3906LT1G
R164 R166 = 150R2F-1-GP: CHIP RES 150 F 1/16W 0402; Category: VR_DDR; DESCRIPTIO: CHIP RES 150 F 1/16W 0402; GREENDFACTOR: R2_SA;HF_SA;G_SA;; Package Type: SMD-RG; Part Number: 64.15005.6DL; Part Type: SMD-RG; SPEC: http://wpqssvr.wistron.com.tw:7001/wpqs/servlet/COM.qpart.Attachment?PartNumber=64.15005.6DL; VENDORPARTNUMBER: RM04FTN1500 / RTT021500FTH / RR0510S-1500-FN / RC0402FR-07150RL/WR04X1500FTL
R253 R976 = 4K7R2J-2-GP: CHIP RES 4.7K J 1/16W 0402; Category: CPU SIDE BAND; GREENDFACTOR: R_SA;HF_SA;G_SA;; Part Number: 63.47234.1DL; Quotation: 8_1; Type: SMD
R973 = 23K7R2F-GP: CHIP RES 23.7K F 1/16W 0402; Category: CPU SIDE BAND; DESCRIPTIO: CHIP RES 23.7K F 1/16W 0402; GREENDFACTOR: R2_SA;HF_SA;G_SA;; Package Type: SMD-RG; Part Number: 64.23725.6DL; Part Type: SMD-RG; SPEC: http://wpqssvr.wistron.com.tw:7001/wpqs/servlet/COM.qpart.Attachment?PartNumber=64.23725.6DL; VENDORPARTNUMBER: RC0402FR-0723K7L/RM04FTN2372/RTT022372FTH/RR0510S-2372-FN
TP349 = TPAD24: 24 MILS TEST PAD; Category: CPU SIDE BAND; Part Number: ZZ.PAD24.001; Part Type: DISCRET2
U25 = SNLVC1G126DCKR-GP: IC CMOS SN74LVC1G126DCKR SC70; GREENDFACTOR: R2_SA;HF_SA;; Package Type: TTL-G; Part Number: 73.1G126.DHG; SPEC: http://wpqssvr.wistron.com.tw:7001/wpqs/servlet/COM.qpart.Attachment?PartNumber=73.1G126.DHG
U83 = SNLVC1G08DCKRG4-GP: IC CMOS SN74LVC1G08DCKRG4 DCK; Alternate: 73.01G08.CAH,73.01G08.L04,73.01G08.DAH; Category: CPU SIDE BAND; DESCRIPTIO: IC CMOS SN74LVC1G08DCKRG4 DCK; GREENDFACTOR: R2_SA;HF_SA;G_SA;; Package Type: TTL-G; Part Number: 73.01G08.DHG; Part Type: TTL-G; SPEC: http://wpqssvr.wistron.com.tw:7001/wpqs/servlet/COM.qpart.Attachment?PartNumber=73.01G08.DHG; VENDORPARTNUMBER: SN74LVC1G08DCKRG4
U108 = SSLVC1G74DC-GP: IC CMOS 74LVC1G74DC VSSOP-8P; Category: CPU SIDE BAND; GREENDFACTOR: R2_SA;HF_SA;; Package Type: TTL-G; Part Number: 73.01G74.CHF; SPEC: http://wpqssvr.wistron.com.tw:7001/wpqs/servlet/COM.qpart.Attachment?PartNumber=73.01G74.CHF
U176 = 74LVC2G14GW-1-GP: IC CMOS 74LVC2G14GW SC-88; GREENDFACTOR: R2_SA;; Package Type: DISCRET-G; Part Number: 73.02G14.0HJ; SPEC: http://wpqssvr.wistron.com.tw:7001/wpqs/servlet/COM.qpart.Attachment?PartNumber=73.02G14.0HJ
R78 R129 = 0R2J-2-GP: CHIP RES 0 J 1/16W 0402; GREENDFACTOR: R2_SA;HF_SA;G_SA;; Package Type: SMD-RG; Part Number: 63.R0034.1DL; SPEC: http://wpqssvr.wistron.com.tw:7001/wpqs/servlet/COM.qpart.Attachment?PartNumber=63.R0034.1DL
R723 R935 = 0R2J-2-GP: CHIP RES 0 J 1/16W 0402; Category: LOM - i350; DESCRIPTIO: CHIP RES 0 J 1/16W 0402; GREENDFACTOR: R2_SA;HF_SA;G_SA;; Package Type: SMD-RG; Part Number: 63.R0034.1DL; Part Type: SMD-RG; SPEC: http://wpqssvr.wistron.com.tw:7001/wpqs/servlet/COM.qpart.Attachment?PartNumber=63.R0034.1DL; VENDORPARTNUMBER: RM04JTN0/RTT02000JTH/RR0510X-000-XN/RC0402JR-070RL/WR04X000 PTL
R932 R933 = 0R2J-2-GP: CHIP RES 0 J 1/16W 0402; Category: LOM - i350; DESCRIPTIO: CHIP RES 0 J 1/16W 0402; GREENDFACTOR: R2_SA;HF_SA;G_SA;; POP?: NOPOP; Package Type: SMD-RG; Part Number: 63.R0034.1DL; Part Type: SMD-RG; SPEC: http://wpqssvr.wistron.com.tw:7001/wpqs/servlet/COM.qpart.Attachment?PartNumber=63.R0034.1DL; VENDORPARTNUMBER: RM04JTN0/RTT02000JTH/RR0510X-000-XN/RC0402JR-070RL/WR04X000 PTL
R977 = 49K9R2F-L-GP: CHIP RES 49.9K F 1/16W 0402; Category: CPU SIDE BAND; DESCRIPTIO: CHIP RES 49.9K F 1/16W 0402; GREENDFACTOR: R2_SA;HF_SA;G_SA;; POP?: POP; Package Type: SMD-RG; Part Number: 64.49925.6DL; Part Type: SMD-RG; SPEC: http://wpqssvr.wistron.com.tw:7001/wpqs/servlet/COM.qpart.Attachment?PartNumber=64.49925.6DL; VENDORPARTNUMBER: RM04FTN4992 / RTT024992FTH / RR0510S-4992-FN / RC0402FR-0749K9L / WR04X4992FTL
R980 R981 R1097 R1107 R1108 = 0R2J-2-GP: CHIP RES 0 J 1/16W 0402; Category: CPU SIDE BAND; DESCRIPTIO: CHIP RES 0 J 1/16W 0402; GREENDFACTOR: R2_SA;HF_SA;G_SA;; Package Type: SMD-RG; Part Number: 63.R0034.1DL; Part Type: SMD-RG; SPEC: http://wpqssvr.wistron.com.tw:7001/wpqs/servlet/COM.qpart.Attachment?PartNumber=63.R0034.1DL; VENDORPARTNUMBER: RM04JTN0/RTT02000JTH/RR0510X-000-XN/RC0402JR-070RL/WR04X000 PTL
R984 = 15KR2F-GP: CHIP RES 15K F 1/16W 0402; Category: CPU SIDE BAND; DESCRIPTIO: CHIP RES 15K F 1/16W 0402; GREENDFACTOR: R2_SA;HF_SA;G_SA;; Package Type: RCL_GP; Part Number: 64.15025.6DL; Part Type: RCL_GP; SPEC: http://wpqssvr.wistron.com.tw:7001/wpqs/servlet/COM.qpart.Attachment?PartNumber=64.15025.6DL; VENDORPARTNUMBER: RM04FTN1502/RTT021502FTH/RR0510S-153-FN/RC0402FR-0715KL
U86 U98 = TSLVC32APW-4-GP: IC CMOS 74LVC32APW TSSOP 14P; Category: CPU SIDE BAND; GREENDFACTOR: R2_SA;R_SA;; Package Type: TTL-G; Part Number: 73.07432.EHB; SPEC: http://wpqssvr.wistron.com.tw:7001/wpqs/servlet/COM.qpart.Attachment?PartNumber=73.07432.EHB
U87 U89 U99 U100 = 7SZ373P6X-GP: IC CMOS NC7SZ373P6X SC70-6; Category: CPU SIDE BAND; GREENDFACTOR: R2_SA;HF_SA;; Package Type: DISCRET-G8; Part Number: 73.7S373.0AJ; SPEC: http://wpqssvr.wistron.com.tw:7001/wpqs/servlet/COM.qpart.Attachment?PartNumber=73.7S373.0AJ
U88 U90 = SNLVC1G17DCKR-GP: IC CMOS SN74LVC1G17DCKR DCK 5P; Category: CPU SIDE BAND; GREENDFACTOR: R2_SA;; Package Type: TTL-G; Part Number: 73.01G17.BHH; SPEC: http://wpqssvr.wistron.com.tw:7001/wpqs/servlet/COM.qpart.Attachment?PartNumber=73.01G17.BHH
R124 R127 R1094 R1095 = 4K7R2F-GP: CHIP RES 4.7K F 1/16W 0402; Category: CPU SIDE BAND; Part Number: 64.47015.6DL; Part Type: RCL_GP
R1096 = 2K21R2F-GP: CHIP RES 2.21K F 1/16W 0402; Category: CPU SIDE BAND; GREENDFACTOR: R_SA;HF_SA;G_SA;; Part Number: 64.22115.6DL; Quotation: 2_3; Type: SMD
U31 U44 = NTJD4001NT1G-1-GP: IC MOSFET NTJD4001NT1G NC SOT-363 6P; GREENDFACTOR: R2_SA;; Part Number: 75.04001.07C; Part Type: DISCRET-G5; SPEC: http://wpqssvr.wistron.com.tw:7001/wpqs/servlet/COM.qpart.Attachment?PartNumber=75.04001.07C
R101 R102 R107 R108 = 64D9R2F-2-GP: CHIP RES 64.9 F 1/16W 0402; GREENDFACTOR: R2_SA;HF_SA;G_SA;; Package Type: SMD-RG1; Part Number: 64.64R95.6DL; SPEC: http://wpqssvr.wistron.com.tw:7001/wpqs/servlet/COM.qpart.Attachment?PartNumber=64.64R95.6DL
R1098 R1099 R1102 R1103 = 300R2J-4-GP: CHIP RES 300 J 1/16W 0402; Category: CPU SIDE BAND; GREENDFACTOR: R2_SA;HF_SA;G_SA;; Package Type: SMD-RG; Part Number: 63.30134.1DL; SPEC: http://wpqssvr.wistron.com.tw:7001/wpqs/servlet/COM.qpart.Attachment?PartNumber=63.30134.1DL
R1100 R1101 R1104 R1105 = 35D7R2F-1-GP: CHIP RES 35.7 F 1/16W 0402; Category: CPU SIDE BAND; GREENDFACTOR: R2_SA;HF_SA;G_SA;; Package Type: SMD-RG3; Part Number: 64.35R75.6DL; SPEC: http://wpqssvr.wistron.com.tw:7001/wpqs/servlet/COM.qpart.Attachment?PartNumber=64.35R75.6DL

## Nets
GND: C1.2 C2.2 C3.2 C4.2 C5.2 C6.2 C7.2 C8.2 C9.2 C10.2 C11.2 C12.2 C13.2 C54.2 C55.2 C57.2 C58.2 C60.2 C61.2 C63.2 C64.2 C66.2 C69.2 C72.2 C73.2 C75.2 R24.1 R26.1 R33.1 R35.1 R45.2 R46.2 R49.2 R55.2 R56.2 R59.2 R68.2 R70.2 R77.2 R79.2 R88.1 R89.2 R106.2 R112.2 R965.2 R973.2 R977.2 R980.2 R981.2 R984.2 R1097.1 R1098.2 R1099.2 R1102.2 R1103.2 R1107.2 R1108.2 U3.7(GND) U3.8(GND) U3.11(GND) U4.7(GND) U4.8(GND) U4.11(GND) U5.7(GND) U6.7(GND) U6.8(GND) U6.11(GND) U7.7(GND) U7.8(GND) U7.11(GND) U8.7(GND) U8.8(GND) U8.11(GND) U16.7(GND) U16.8(GND) U16.11(GND) U17.7(GND) U17.8(GND) U17.11(GND) U25.3(GND) U31.1(S1) U31.4(S2) U44.1(S1) U44.4(S2) U83.3(GND) U86.7(GND) U87.2(GND) U88.3(GND) U89.2(GND) U90.3(GND) U97.7(GND) U98.7(GND) U98.9(I0) U98.10(I1) U98.12(I0) U98.13(I1) U99.2(GND) U100.2(GND) U108.4(GND) U176.2(GND) ; also on sheet 1 2 3 4 5 6 7 8 9 10 11 12 13 14 15 16 17 18 19 20 21 22 23 24 25 26 27 28 29 30 31 32 33 34 35 36 37 38 39 44 46 47 49 50 51 52 53 54 55 56 57 58 59 60 61 62 63 64 65 66 69 70 71 73 74 75 76 78 79 80 81 82 83 84 86 87 88 89 90 91 92 93 94 95 104 105 106 107 108 109 110 111 112 113 114 115 116 117 118 119 128 129 138 139 159 160 161 166 168 169 170 171 172 173 174 175 176 177 180 181 182 183 184
P0V7_CPU0_ERRS_VREF: C2.1 R41.2 R46.1 U3.4(VREF)
P0V7_CPU1_ERRS_VREF: C4.1 R51.2 R56.1 U4.4(VREF)
P0V7_GTL_VREF_0: C7.1 R67.2 R70.1 U6.4(VREF)
P0V7_GTL_VREF_1: C9.1 R75.2 R79.1 U7.4(VREF)
P0V7_GTL_VREF_2: C11.1 R83.2 R89.1 U8.4(VREF)
P3V3: C1.1 C3.1 C5.1 C6.1 C8.1 C10.1 C54.1 C55.1 C57.1 C58.1 C282.1 Q12.E R124.1 R127.1 R253.2 U3.14(VCC) U4.14(VCC) U5.14(VCC) U6.14(VCC) U7.14(VCC) U8.14(VCC) U25.5(VCC) U83.5(VCC) U108.8(VCC) U176.5(VCC) ; also on sheet 1 3 8 45 46 48 49 52 54 58 65 74 76 78 83 84 87 90 91 94 95 161 166 168 173 174 177 180 181 182 183
P3V3_STBY: C12.1 C13.1 C60.1 C61.1 C63.1 C64.1 C66.1 C69.1 C72.1 C73.1 C75.1 C283.1 C363.1 R105.1 R111.1 R1094.1 R1095.1 U16.14(VCC) U17.14(VCC) U86.14(VCC) U87.5(VCC) U88.5(VCC) U89.5(VCC) U90.5(VCC) U97.14(VCC) U98.14(VCC) U99.5(VCC) U100.5(VCC) ; also on sheet 2 3 5 6 8 9 10 11 12 15 16 17 20 21 22 25 26 27 30 31 33 34 35 37 38 39 45 47 49 50 51 52 54 55 59 60 61 62 63 64 65 66 69 70 71 72 73 74 76 79 83 84 87 88 89 90 91 92 93 94 95 159 161 166 168 173 174 176 177 179 180 182 183 184
PVCCIO: R23.1 R25.1 R27.1 R29.1 R30.1 R31.1 R32.1 R34.1 R36.1 R38.1 R39.1 R40.1 R41.1 R42.1 R43.1 R44.1 R51.1 R52.1 R53.1 R54.1 R67.1 R69.1 R75.1 R76.1 R83.1 R84.1 R85.1 R86.1 R87.1 R103.1 R104.1 R109.1 R110.1 R164.1 R166.1 ; also on sheet 11 16 26 35 39 46 47 68 87 120 129 130 139 160 173 177 179 182
PVDDQ_AB: R101.1 ; also on sheet 28 30 45 52 116 117 118 119 130 139
PVDDQ_CD: R102.1 ; also on sheet 23 25 45 112 113 114 115 130 139
PVDDQ_EF: R107.1 ; also on sheet 18 20 45 108 109 110 111 120 129
PVDDQ_GH: R108.1 ; also on sheet 13 15 45 104 105 106 107 120 129
CPU0_ERR2_N: R63.2 ; also on sheet 180
CPU0_THERMTRIP_OE_N: R981.1 U87.6(OE#)
CPU1_ERR2_N: R66.2 ; also on sheet 180
CPU1_THERMTRIP_OE_N: R980.1 U89.6(OE#)
CPU_DIMM_EVENT_LV_SHIFT: R1094.2 U31.5(G2) U31.6(D1)
FM_CATERR_DLY: U176.3(2A) U176.6(1Y)
FM_CATERR_DLY_BUF_N: R969.2 U25.4(Y)
FM_CATERR_DLY_FF_Q: R976.2 U108.5(Q)
FM_CATERR_DLY_FF_Q_R: Q12.B R976.1
FM_CATERR_DLY_N: U25.2(A) U176.4(2Y)
FM_CATERR_RC_N: C282.2 R972.1 U176.1(1A)
FM_CATERR_RC_R_N: Q12.C R972.2 R973.1
FM_CPLD_PCH_CATERR_MSMI_N: U108.7(S#D) ; also on sheet 52
FM_CPU0_ERR0_LVT3_N: R47.2 U5.1(I)
FM_CPU0_ERR0_LVT3_N_R: R61.1 U5.2(O)
FM_CPU0_ERR0_LVT3_R_N: R47.1 U3.9(A3)
FM_CPU0_ERR1_LVT3_N: R48.2 U5.3(I)
FM_CPU0_ERR1_LVT3_N_R: R62.1 U5.4(O)
FM_CPU0_ERR1_LVT3_R_N: R48.1 U3.10(A2)
FM_CPU0_ERR2_LVT3_N: R50.2 U5.5(I)
FM_CPU0_ERR2_LVT3_N_R: R63.1 U5.6(O)
FM_CPU0_ERR2_LVT3_R_N: R50.1 U3.12(A1)
FM_CPU0_FIVR_FAULT_CO_D_N: R124.2 U44.3(D2) U98.1(I0)
FM_CPU0_FIVR_FAULT_LVC3_N: U98.3(O) U99.3(D)
FM_CPU0_FIVR_FAULT_LVT3: R71.2 U44.5(G2)
FM_CPU0_FIVR_FAULT_LVT3_N: U99.4(Q) ; also on sheet 74
FM_CPU0_FIVR_FAULT_LVT3_R_N: R71.1 U6.13(A0)
FM_CPU0_PROCHOT_LVT3_N: R72.2 ; also on sheet 180
FM_CPU0_PROCHOT_LVT3_R_N: R72.1 U6.12(A1)
FM_CPU0_PWRGD_PORST: U86.2(I1) U86.4(I0) U90.4(Y)
FM_CPU0_THERMTRIP_LATCH_LVC3_N: R723.2 U87.4(Q)
FM_CPU0_THERMTRIP_LVC3_N: R723.1 R932.1 U98.2(I1) ; also on sheet 76
FM_CPU0_THERMTRIP_LVC3_N_R: R932.2 U86.8(O) U87.3(D)
FM_CPU0_THERMTRIP_LVT3_N: R73.2 U86.9(I0) U97.1(I)
FM_CPU0_THERMTRIP_LVT3_R_N: R73.1 U6.10(A2)
FM_CPU1_ERR0_LVT3_N: R57.2 U5.9(I)
FM_CPU1_ERR0_LVT3_N_R: R64.1 U5.8(O)
FM_CPU1_ERR0_LVT3_R_N: R57.1 U4.9(A3)
FM_CPU1_ERR1_LVT3_N: R58.2 U5.11(I)
FM_CPU1_ERR1_LVT3_N_R: R65.1 U5.10(O)
FM_CPU1_ERR1_LVT3_R_N: R58.1 U4.10(A2)
FM_CPU1_ERR2_LVT3_N: R60.2 U5.13(I)
FM_CPU1_ERR2_LVT3_N_R: R66.1 U5.12(O)
FM_CPU1_ERR2_LVT3_R_N: R60.1 U4.12(A1)
FM_CPU1_FIVR_FAULT_CO_D_N: R127.2 U44.6(D1) U98.4(I0)
FM_CPU1_FIVR_FAULT_LVC3_N: U98.6(O) U100.3(D)
FM_CPU1_FIVR_FAULT_LVT3: R81.2 U44.2(G1)
FM_CPU1_FIVR_FAULT_LVT3_N: U100.4(Q) ; also on sheet 74
FM_CPU1_FIVR_FAULT_LVT3_R_N: R81.1 U7.13(A0)
FM_CPU1_PROCHOT_LVT3_N: R82.2 ; also on sheet 180
FM_CPU1_PROCHOT_LVT3_R_N: R82.1 U7.12(A1)
FM_CPU1_THERMTRIP_LATCH_LVC3_N: R935.2 U89.4(Q)
FM_CPU1_THERMTRIP_LVC3_N: R933.1 R935.1 U98.5(I1) ; also on sheet 76
FM_CPU1_THERMTRIP_LVC3_N_R: R933.2 U86.11(O) U89.3(D)
FM_CPU1_THERMTRIP_LVT3_N: R80.2 U86.13(I1) U97.3(I)
FM_CPU1_THERMTRIP_LVT3_R_N: R80.1 U7.10(A2)
FM_CPU_CATERR_LVT3_N: R74.2 ; also on sheet 52 74
FM_CPU_CATERR_LVT3_R_N: R74.1 U6.9(A3)
FM_CPU_DIMM_EVENT_CO_N: R1096.2 U31.2(G1) ; also on sheet 104 105 106 107 108 109 110 111 112 113 114 115 116 117 118 119
FM_CPU_ERR0_CO_N: R61.2 R64.2 ; also on sheet 166 177
FM_CPU_ERR1_CO_N: R62.2 R65.2 ; also on sheet 51 177
FM_CPU_MSMI_LVT3_BMC_N: R361.2 ; also on sheet 52 177
FM_CPU_MSMI_LVT3_R_N: R361.1 U7.9(A3)
FM_CPU_PROCHOT_N: U97.10(O) U97.12(O) ; also on sheet 48
FM_CPU_THERMTRIP_PORST: U86.10(I1) U86.12(I0) U88.4(Y)
FM_LVC3_CPU0_PWRGD: R78.2 U87.1(LE) U99.1(LE)
FM_LVC3_CPU0_PWRGD_R: R78.1 U86.3(O)
FM_LVC3_CPU1_PWRGD: R129.2 U89.1(LE) U100.1(LE)
FM_LVC3_CPU1_PWRGD_R: R129.1 U86.6(O)
FM_LVC3_CPU_CATERR_N: U83.4(Y) U108.6(R#D)
FM_MEM_THERM_EVENT_LVT3_N: R1095.2 U31.3(D2) U97.5(I) ; also on sheet 74
FM_THERMTRIP_CO_N: U97.2(O) U97.4(O) U97.6(O) ; also on sheet 51
H_CPU0_CATERR_G_N: R164.2 R961.1 ; also on sheet 139
H_CPU0_ERR0_G_N: R42.2 U3.6(B3) ; also on sheet 139
H_CPU0_ERR1_G_N: R43.2 U3.5(B2) ; also on sheet 139
H_CPU0_ERR2_G_N: R44.2 U3.3(B1) ; also on sheet 139
H_CPU0_FIVR_FAULT_G: U6.2(B0) ; also on sheet 138 179
H_CPU0_MEMAB_MEMHOT_BMC_LVT3_N: R1129.2 ; also on sheet 180
H_CPU0_MEMAB_MEMHOT_G_N: R84.2 U8.6(B3) ; also on sheet 139 181 183
H_CPU0_MEMAB_MEMHOT_LVT3_N: R90.2 R1129.1
H_CPU0_MEMAB_MEMHOT_LVT3_R_N: R90.1 U8.9(A3)
H_CPU0_MEMCD_MEMHOT_BMC_LVT3_N: R1131.2 ; also on sheet 180
H_CPU0_MEMCD_MEMHOT_G_N: R85.2 U8.5(B2) ; also on sheet 139 181 183
H_CPU0_MEMCD_MEMHOT_LVT3_N: R91.2 R1131.1
H_CPU0_MEMCD_MEMHOT_LVT3_R_N: R91.1 U8.10(A2)
H_CPU0_PROCHOT_G_N: R69.2 U6.3(B1) ; also on sheet 139 181 183
H_CPU0_THERMTRIP_G_N: U6.5(B2) ; also on sheet 139 179
H_CPU1_CATERR_G_N: R166.2 R964.1 ; also on sheet 129
H_CPU1_ERR0_G_N: R52.2 U4.6(B3) ; also on sheet 129
H_CPU1_ERR1_G_N: R53.2 U4.5(B2) ; also on sheet 129
H_CPU1_ERR2_G_N: R54.2 U4.3(B1) ; also on sheet 129
H_CPU1_FIVR_FAULT_G: U7.2(B0) ; also on sheet 128 179
H_CPU1_MEMEF_MEMHOT_BMC_LVT3_N: R1133.2 ; also on sheet 180
H_CPU1_MEMEF_MEMHOT_G_N: R86.2 U8.3(B1) ; also on sheet 129 181 183
H_CPU1_MEMEF_MEMHOT_LVT3_N: R92.2 R1133.1
H_CPU1_MEMEF_MEMHOT_LVT3_R_N: R92.1 U8.12(A1)
H_CPU1_MEMGH_MEMHOT_BMC_LVT3_N: R1135.2 ; also on sheet 180
H_CPU1_MEMGH_MEMHOT_G_N: R87.2 U8.2(B0) ; also on sheet 129 181 183
H_CPU1_MEMGH_MEMHOT_LVT3_N: R93.2 R1135.1
H_CPU1_MEMGH_MEMHOT_LVT3_R_N: R93.1 U8.13(A0)
H_CPU1_PROCHOT_G_N: R76.2 U7.3(B1) ; also on sheet 129 181 183
H_CPU1_THERMTRIP_G_N: U7.5(B2) ; also on sheet 129 179
H_CPU_CATERR_G_N: R961.2 R964.2 U6.6(B3)
H_CPU_MSMI_G_N: U7.6(B3) ; also on sheet 179
H_LVT3_CPU0_PROCHOT_OD_N: U97.11(I) ; also on sheet 174 180
H_LVT3_CPU1_PROCHOT_OD_N: U97.13(I) ; also on sheet 174 180
IRQ_CPU_CATERR_DLY: R253.1 R969.1 U83.1(A) ; also on sheet 166
PD_CPU0_BIST_ENABLE: R24.2 ; also on sheet 139
PD_CPU0_ERRS_B0: R49.1 U3.2(B0)
PD_CPU0_ERRS_DIR: R45.1 U3.1(DIR)
PD_CPU0_FIVR_FAULT_OE_N: R1107.1 U99.6(OE#)
PD_CPU0_TXT_PLTEN: R26.2 ; also on sheet 139
PD_CPU1_BIST_ENABLE: R33.2 ; also on sheet 129
PD_CPU1_ERRS_B0: R59.1 U4.2(B0)
PD_CPU1_ERRS_DIR: R55.1 U4.1(DIR)
PD_CPU1_FIVR_FAULT_OE_N: R1108.1 U100.6(OE#)
PD_CPU1_TXT_PLTEN: R35.2 ; also on sheet 129
PD_DIR_0: R68.1 U6.1(DIR)
PD_DIR_1: R77.1 U7.1(DIR)
PD_DIR_2: R88.2 U8.1(DIR)
PD_EU95_9: R1097.2 U97.9(I)
PD_FF_D_CATERR: R965.1 U108.1(CP) U108.2(D)
PD_GTLREF_0: R106.1 U16.4(VREF)
PD_GTLREF_1: R112.1 U17.4(VREF)
PD_PWRGD_PORST: C363.2 R984.1 U90.2(A)
PD_THERMTRIP_PORST: C283.2 R977.1 U88.2(A)
PU_CPU0_BMCINIT: R25.2 ; also on sheet 139
PU_CPU0_FRMAGENT: R23.2 ; also on sheet 139
PU_CPU0_SAFE_MODE_BOOT: R31.2 ; also on sheet 139
PU_CPU0_SOCKET_ID_0: R29.2 ; also on sheet 139
PU_CPU0_SOCKET_ID_1: R30.2 ; also on sheet 139
PU_CPU0_TXT_AGENT: R27.2 ; also on sheet 139
PU_CPU1_BMCINIT: R34.2 ; also on sheet 129
PU_CPU1_FRMAGENT: R32.2 ; also on sheet 129
PU_CPU1_SAFE_MODE_BOOT: R40.2 ; also on sheet 129
PU_CPU1_SOCKET_ID_0: R38.2 ; also on sheet 129
PU_CPU1_SOCKET_ID_1: R39.2 ; also on sheet 129
PU_CPU1_TXT_AGENT: R36.2 ; also on sheet 129
PU_DIR_HIGH_0: R105.2 U16.1(DIR)
PU_DIR_HIGH_1: R111.2 U17.1(DIR)
PVPP_AB: R1096.1 ; also on sheet 27 116 117 118 119 160
PWRGD_CPU0_AB_DRAM_G: R1099.1 R1100.1 ; also on sheet 139
PWRGD_CPU0_AB_DRAM_G_R: R101.2 R1100.2 U16.3(B1)
PWRGD_CPU0_CD_DRAM_G: R1098.1 R1101.1 ; also on sheet 139
PWRGD_CPU0_CD_DRAM_G_R: R102.2 R1101.2 U16.2(B0)
PWRGD_CPU0_G: R103.2 U16.6(B3) ; also on sheet 47 139
PWRGD_CPU0_LVC3: U16.9(A3) ; also on sheet 51
PWRGD_CPU1_EF_DRAM_G: R1103.1 R1104.1 ; also on sheet 129
PWRGD_CPU1_EF_DRAM_G_R: R107.2 R1104.2 U17.3(B1)
PWRGD_CPU1_G: R109.2 U17.6(B3) ; also on sheet 129
PWRGD_CPU1_GH_DRAM_G: R1102.1 R1105.1 ; also on sheet 129
PWRGD_CPU1_GH_DRAM_G_R: R108.2 R1105.2 U17.2(B0)
PWRGD_CPU1_LVC3: U17.9(A3) ; also on sheet 51
PWRGD_DRAMPWRGD_CO: U16.12(A1) U16.13(A0) U17.12(A1) U17.13(A0) ; also on sheet 90
RST_CPU0_G_N: R104.2 U16.5(B2) ; also on sheet 47 139
RST_CPU0_LVC3_N: U16.10(A2) U86.1(I0) ; also on sheet 51
RST_CPU1_G_N: R110.2 U17.5(B2) ; also on sheet 129
RST_CPU1_LVC3_N: U17.10(A2) U86.5(I1) ; also on sheet 51
RST_PLTRST_N: U25.1(OE) U83.2(B) ; also on sheet 51 90 174 177
TP_CATERR_DLY_FF_Q_N: TP349.1 U108.3(Q#)

Not connected (* = marked no-connect by the designer): U3 13(A0)*; U4 13(A0)*; U88 1(NC#1)*; U90 1(NC#1)*; U97 8(O)*; U98 8(O)* 11(O)*

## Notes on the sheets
sheet 96
- CPU SIDE BAND - FIVR FAULT
- FAB2 REV003 20150721
- TO BMC
- FROM VOLTAGE
  TRANSLATOR
  TO GTL LVT3
- Change to 75.04001.07C
- TO BMC
sheet 97
- CPU SIDE BAND - RST & PG
- CPU0
- Place close to CPU0 within 2.5".
- PDG P.233
- Rpu = 65ohm in PDG p.578
- CAD NOTE:
  * PLACE CLOSE TO VOLTAGE TRANSLATOR.
  * X6S USED TO MEET THERMAL REQUIREMENT.
- TO
  CPU0/CPU XDP
- FROM
  CPLD
- TO
  CPU0
- FROM WBG
- Place close to CPU0
- change to 71.02014.00W
- DESIGN NOTE:
  DRAM_PWR_OK PU AND PD EMPTY FOR JKT (PPO INTERPOSER)
  POPULATE FOR HSX
- DESIGN NOTES:
   - THE GTL2014 IS BEING USED AS LVTTL TO GTL CONVERTER
   SO THE PINS 'AX' ARE INPUTS & THE OUTPUTS ARE OPEN-DRAIN
    AND VREF PIN IS NOT USED
- CPU1
- Place close to CPU0 within 2.5".
- Rpu = 65ohm in PDG p.578
- PDG P.233
- CAD NOTE:
  * PLACE CLOSE TO VOLTAGE TRANSLATOR.
  * X6S USED TO MEET THERMAL REQUIREMENT.
- TO
  CPU1
- FROM
  CPLD
- TO
  CPU1
- Place close to CPU1
- change to 71.02014.00W
- DESIGN NOTE:
  DRAM_PWR_OK PU AND PD EMPTY FOR JKT (PPO INTERPOSER)
  POPULATE FOR HSX
- DESIGN NOTES:
  THE GTL2014 IS BEING USED AS LVTTL TO GTL CONVERTER
  SO THE PINS AX ARE INPUTS & THE OUTPUTS ARE OPEN-DRAIN
  AND VREF PIN IS NOT USED.
sheet 98
- CPU SIDE BAND - DIMM_EVENT
- FAB1 REV013 20150413
- Change to 73.07407.DHB
- TO
  CPLD
- Change to 75.04001.07C
- TO
  WBG
sheet 99
- CPU SIDE BAND - THERMTRIP
- FROM VOLTAGE
  TRANSLATOR
  GTL TO LVT3
- FROM VOLTAGE
  TRANSLATOR
  GTL TO LVT3
sheet 100
- CPU SIDE BAND - CAT. ERROR
- Place close to CPUs within 1".
- VOLTAGE
  TRANSLATOR
  GTL TO LVT3
- FROM
  CPUs
- Intput
- Output
- S_D
- R_D
- CP
- D
- Q
- Q#
- L
- H
- X
- X
- H
- L
- H
- L
- X
- X
- L
- H
- CATERR_N Delay Circuit to WBG
- L
- L
- X
- X
- H
- H
- Intel recommends that the CATERR_N signal be buffered through a 400us
- delay circuits before being connected to a PCH GPIO.
- FAB1 REV004 20150320
- TO
  WBG
- FAB1 REV013 20150413
- FAB1 20150217
- Change to 73.1G126.DHG
sheet 101
- CPU SIDE BAND - LEVEL SHIFT
- Place close to CPU0 within 3".
- PDG P.239
- PDG P.228
- If CATERR_N is routed to a BMC, the BMC should ignore any signals from
  CATERR_N until PWRGOOD is asserted.
- Change to 71.02014.00W
- FAB1 REV005 20150323
- FAB1 20150226
- Change to 71.02014.00W
- Change to 71.02014.00W
sheet 102
- CPU SIDE BAND - ERR CIRCUIT
- DESIGN NOTE:
  * THE GTL2014 IS BEING USED AS GTL TO LVTTL CONVERTER
  SO THE PINS BX ARE INPUTS & THE OUTPUTS ARE PUSHPULL.
  * VREF IS SET AT 2/3 OF VCCIO.
- CPU1 ERROR
- change to 71.02014.00W
- TO PCH
- TO CPLD
- TO BMC
- PDG P.229
- Uncorrected fatal error
- correctable errors
- Uncorrected but recoverable
- errors(non-fatal)
sheet 103
- CPU SIDE BAND - HW STRAPS
- Intel TXT Enabled :
- Intel TXT Disabled :
- CPU0
- CPU1
- CPU0
- CPU1
- FAB1 REV010 20150331
- TXT_AGENT
- PU
- NC
- TXT_AGENT
- NC
- NC
- TXT_PLTEN
- NC
- NC
- TXT_PLTEN
- PD
- PD
- FAB1 REV004 20150320
- ODT - Pull down
- CPU0 = ˉ00b = 0x30
  CPU1 = ˉ01b = 0x31
  CPU2 = ˉ10b = 0x32
  CPU3 = ˉ11b = 0x33
- ODT - Pull down
- FAB1 REV004 20150320
- ODT - Pull down
- CPU0 = ˉ00b = 0x30
  CPU1 = ˉ01b = 0x31
  CPU2 = ˉ10b = 0x32
  CPU3 = ˉ11b = 0x33
- ODT - Pull down
